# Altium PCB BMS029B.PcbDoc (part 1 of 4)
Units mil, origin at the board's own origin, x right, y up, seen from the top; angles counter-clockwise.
Board outline 4950 x 4000 mil, 4 copper layers (Layer 1 - Top Layer, Layer 2 - GND, Layer 3 - Signal, Layer 4 - Bottom Layer), stack 61.4 mil thick; 370 components, 202 nets, 969 pads, 408 vias.
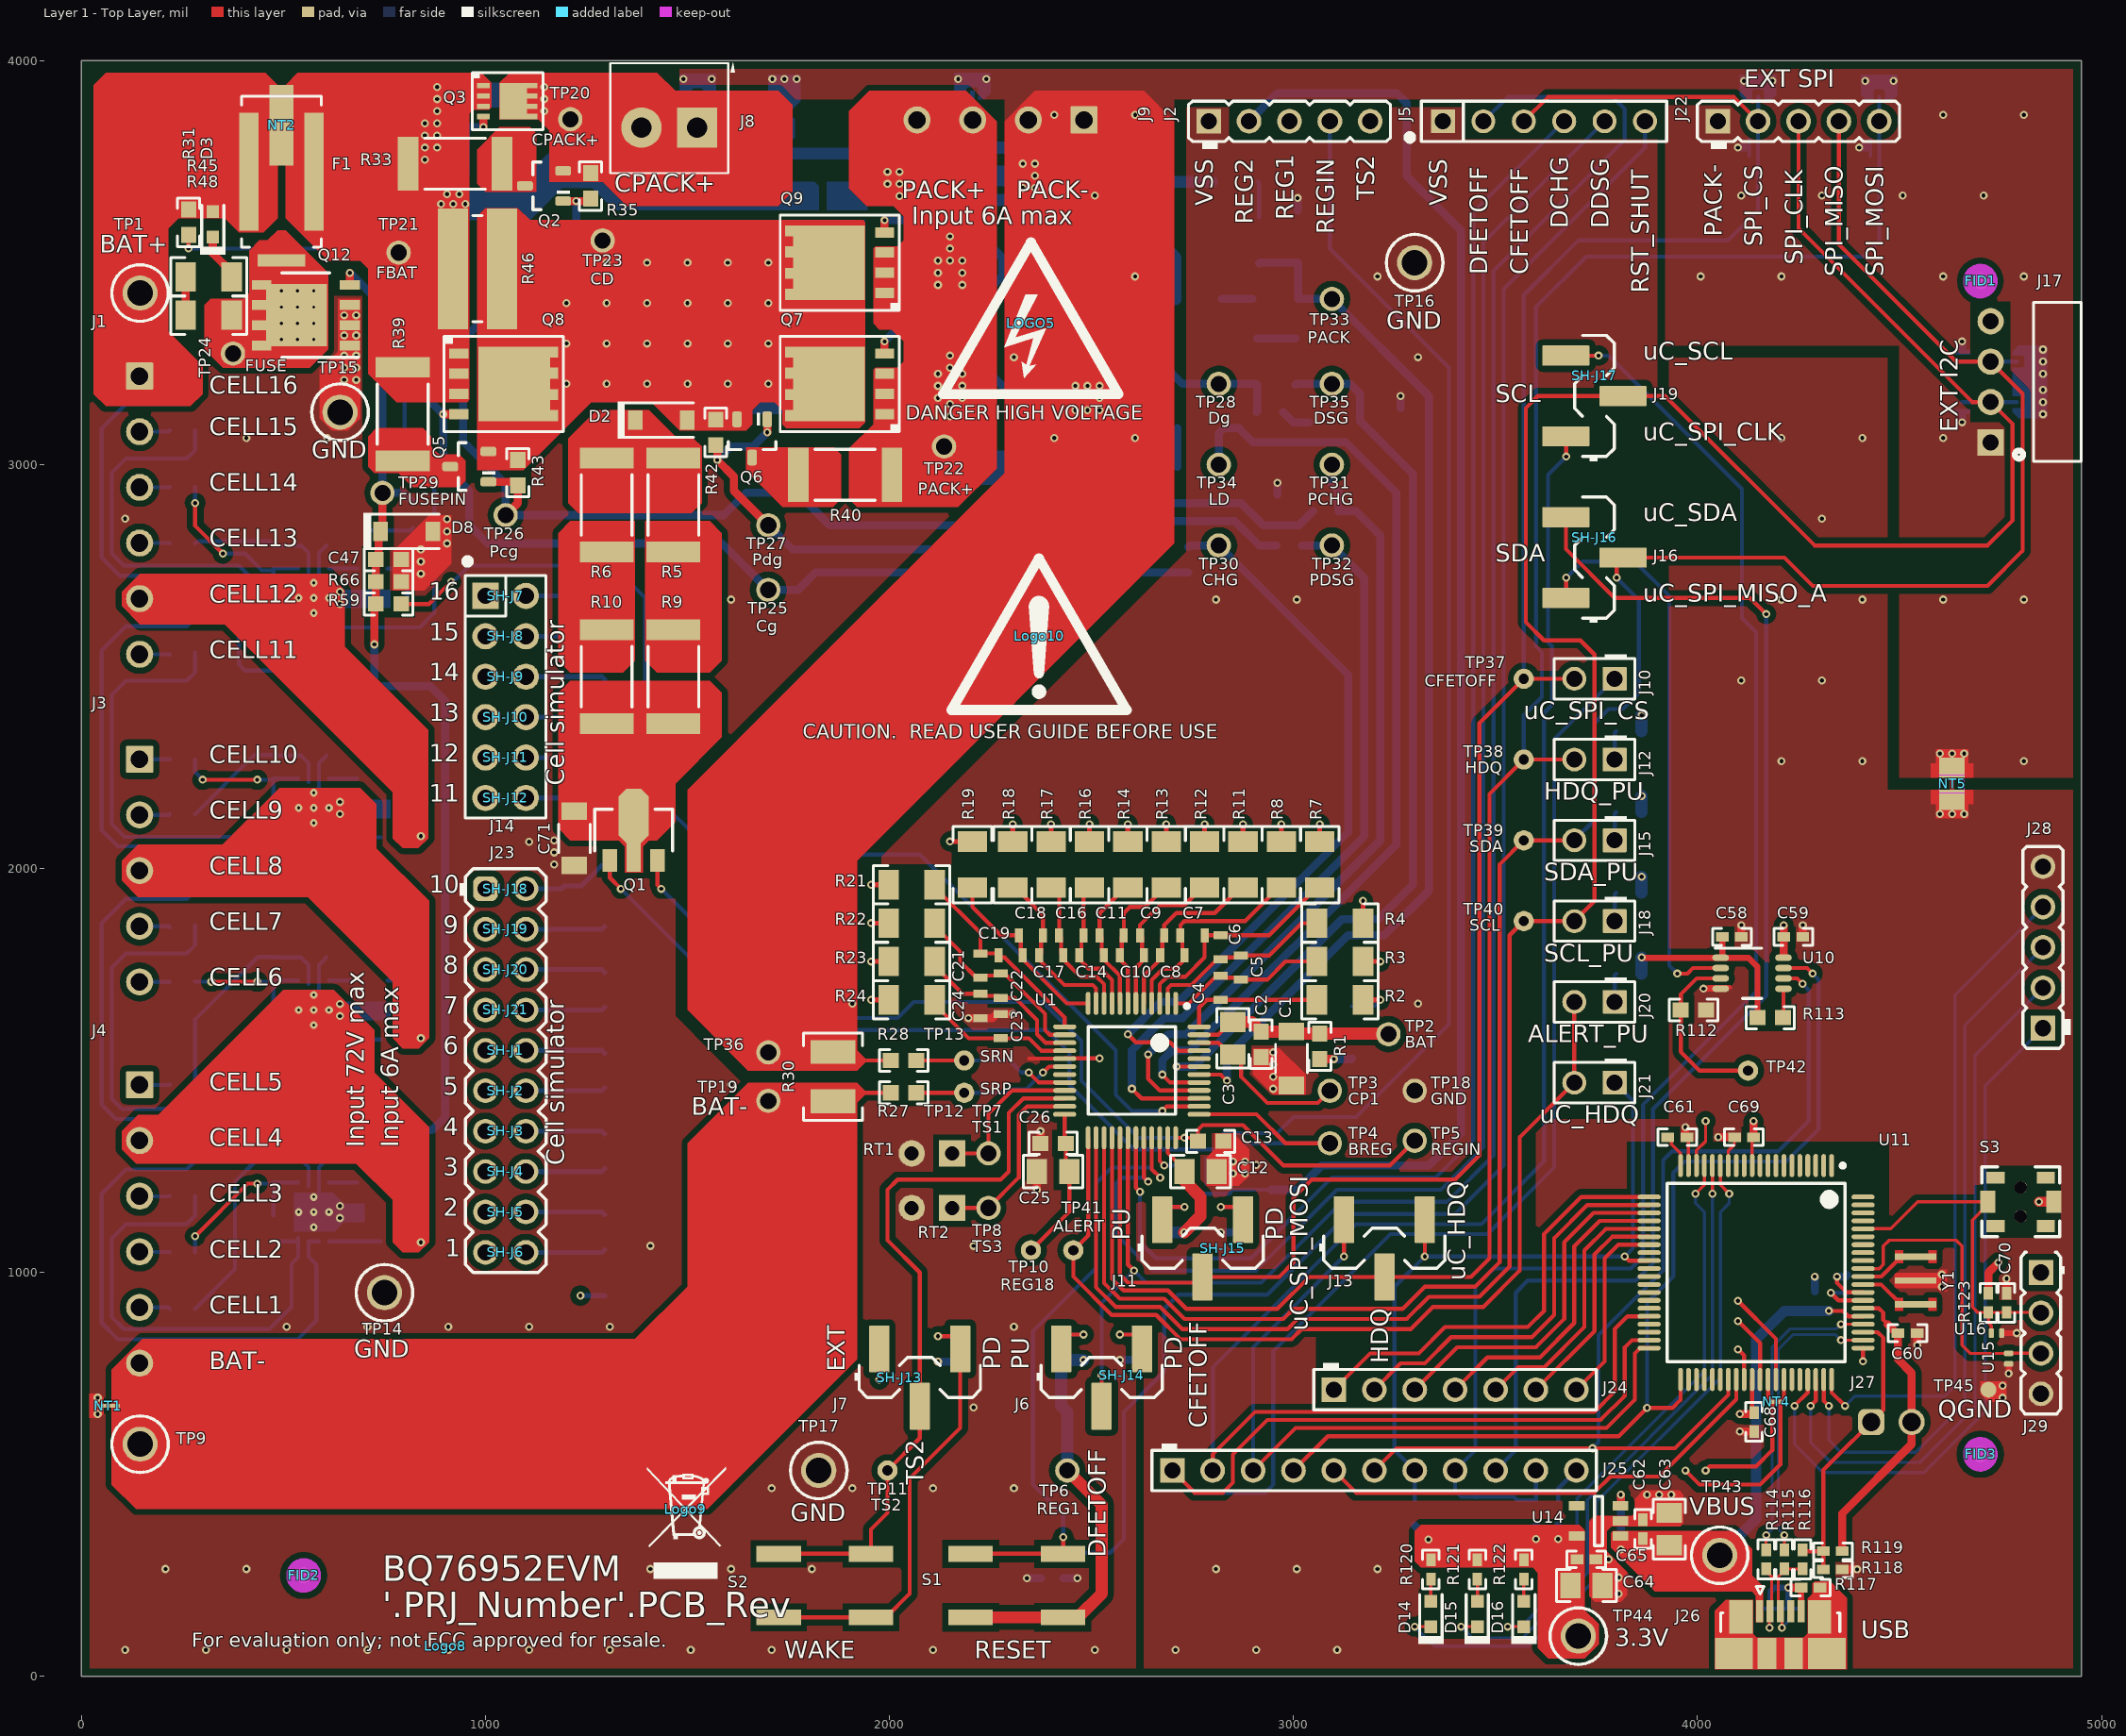
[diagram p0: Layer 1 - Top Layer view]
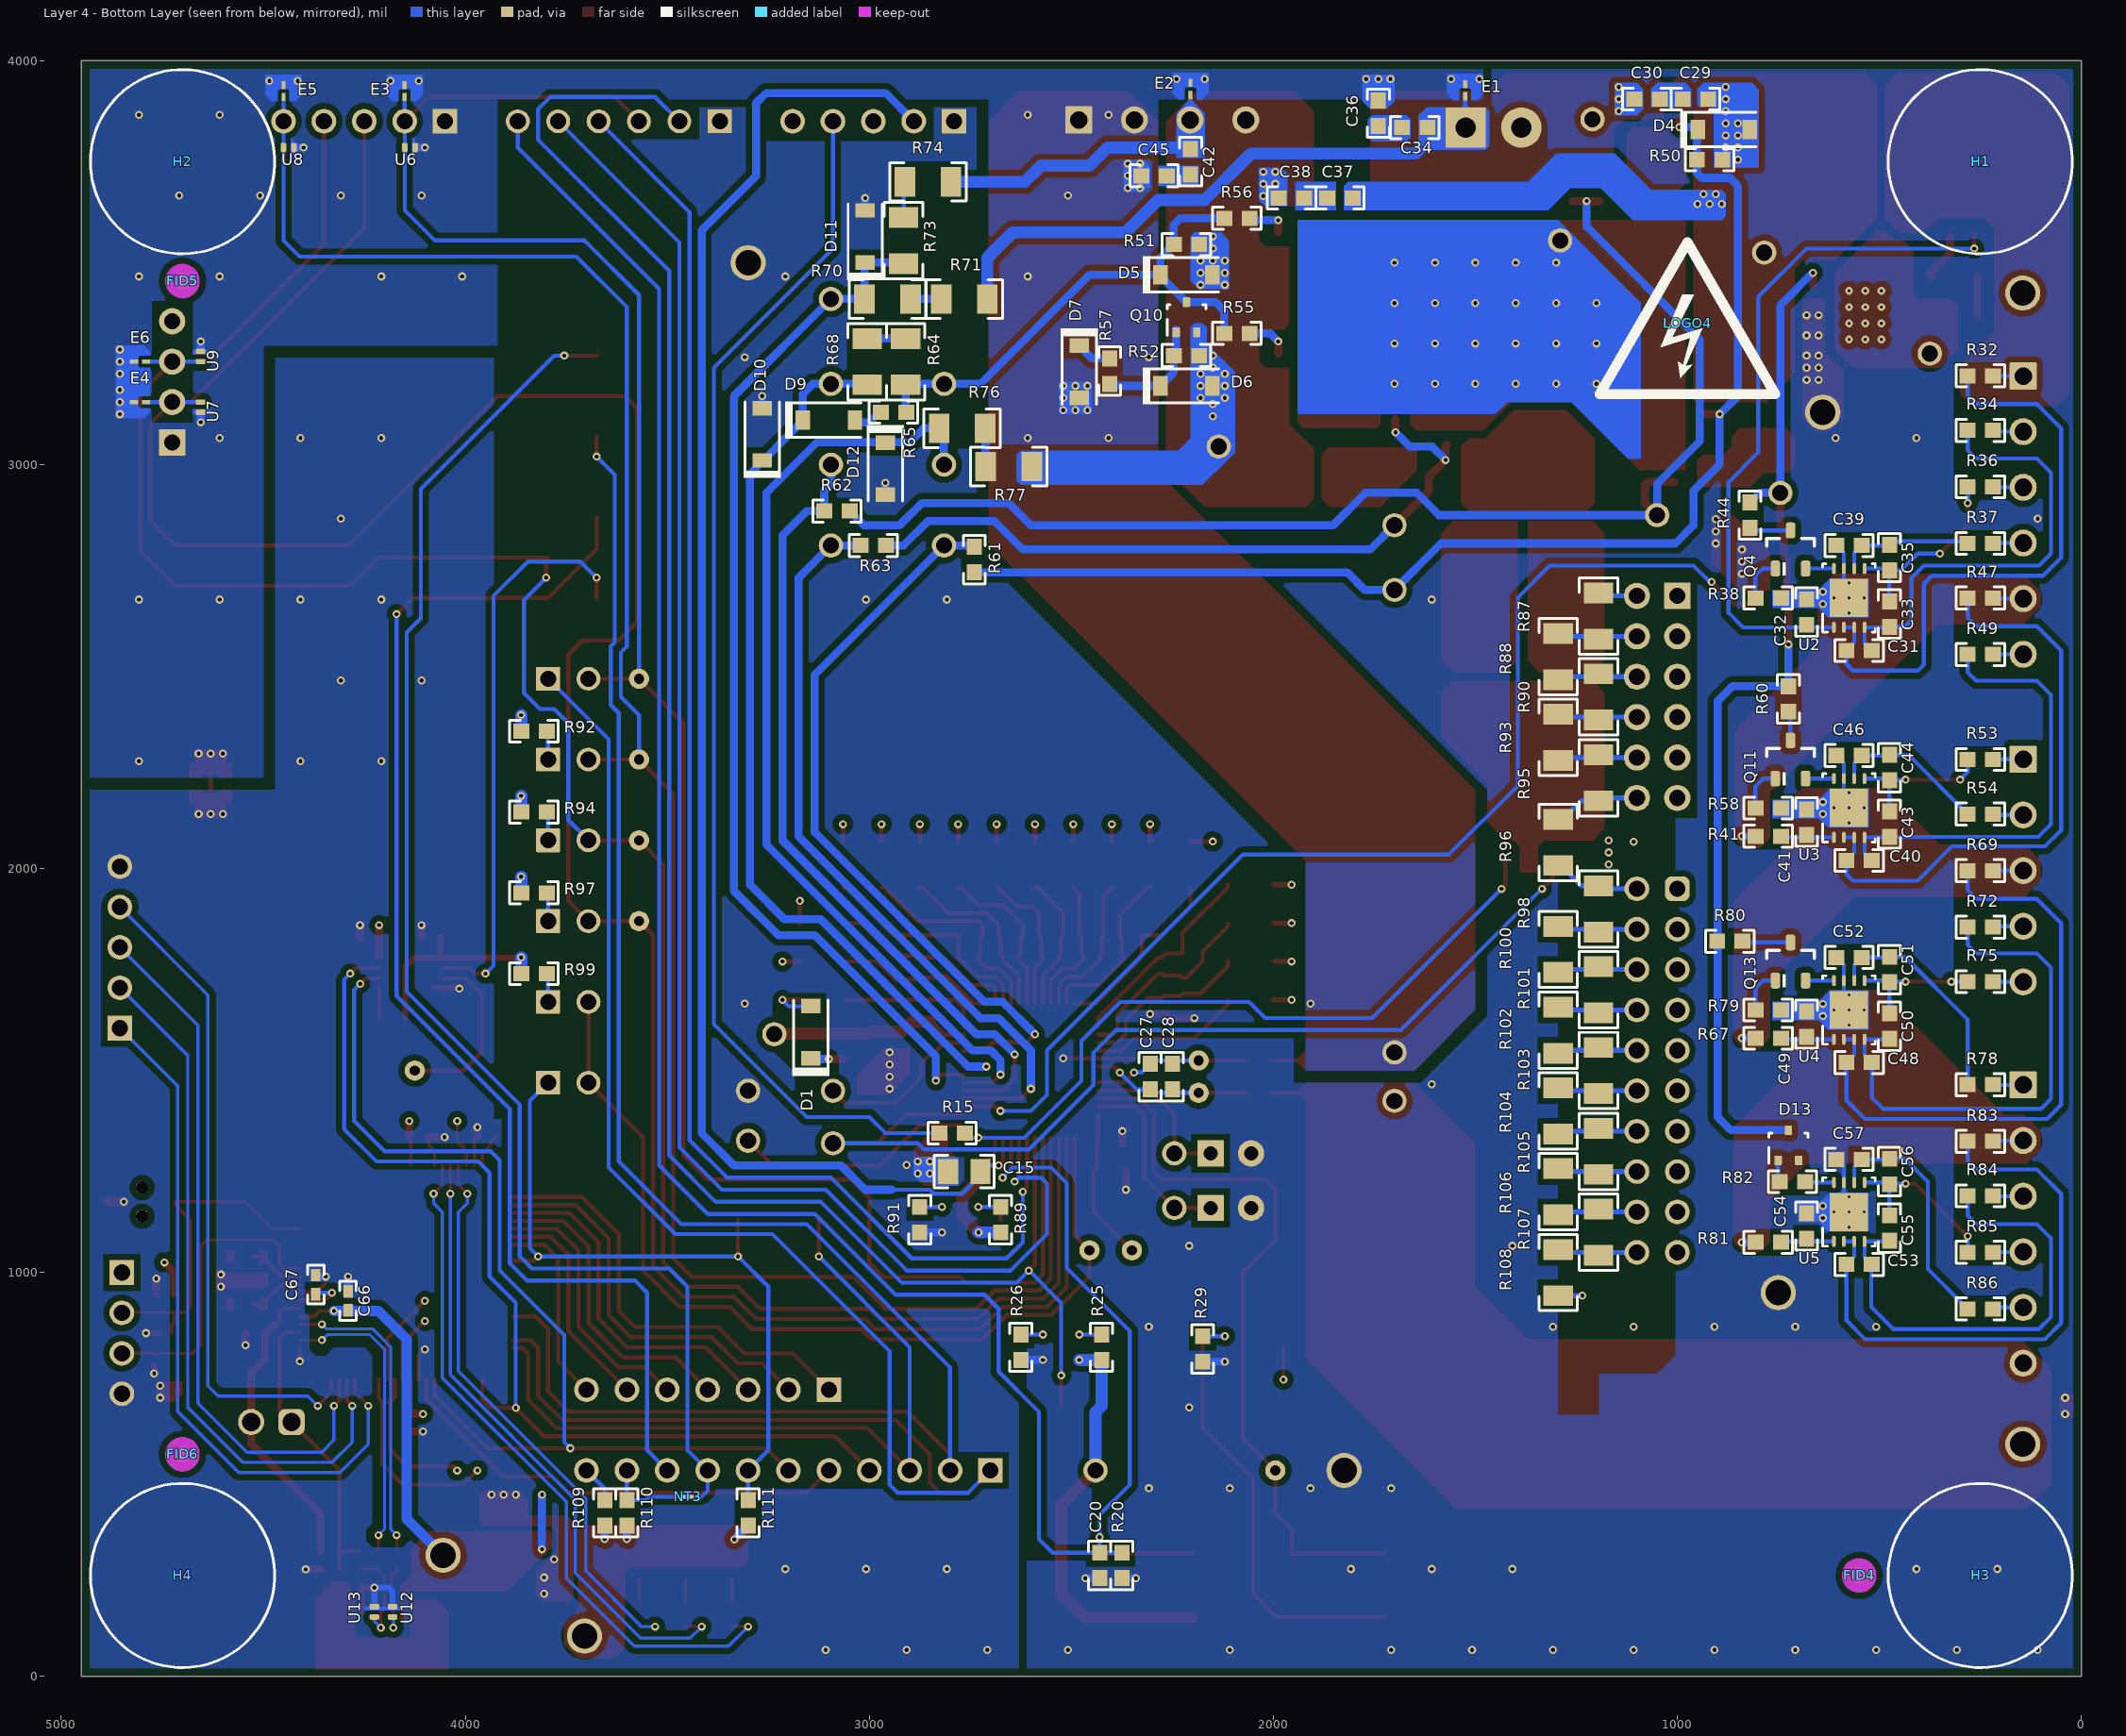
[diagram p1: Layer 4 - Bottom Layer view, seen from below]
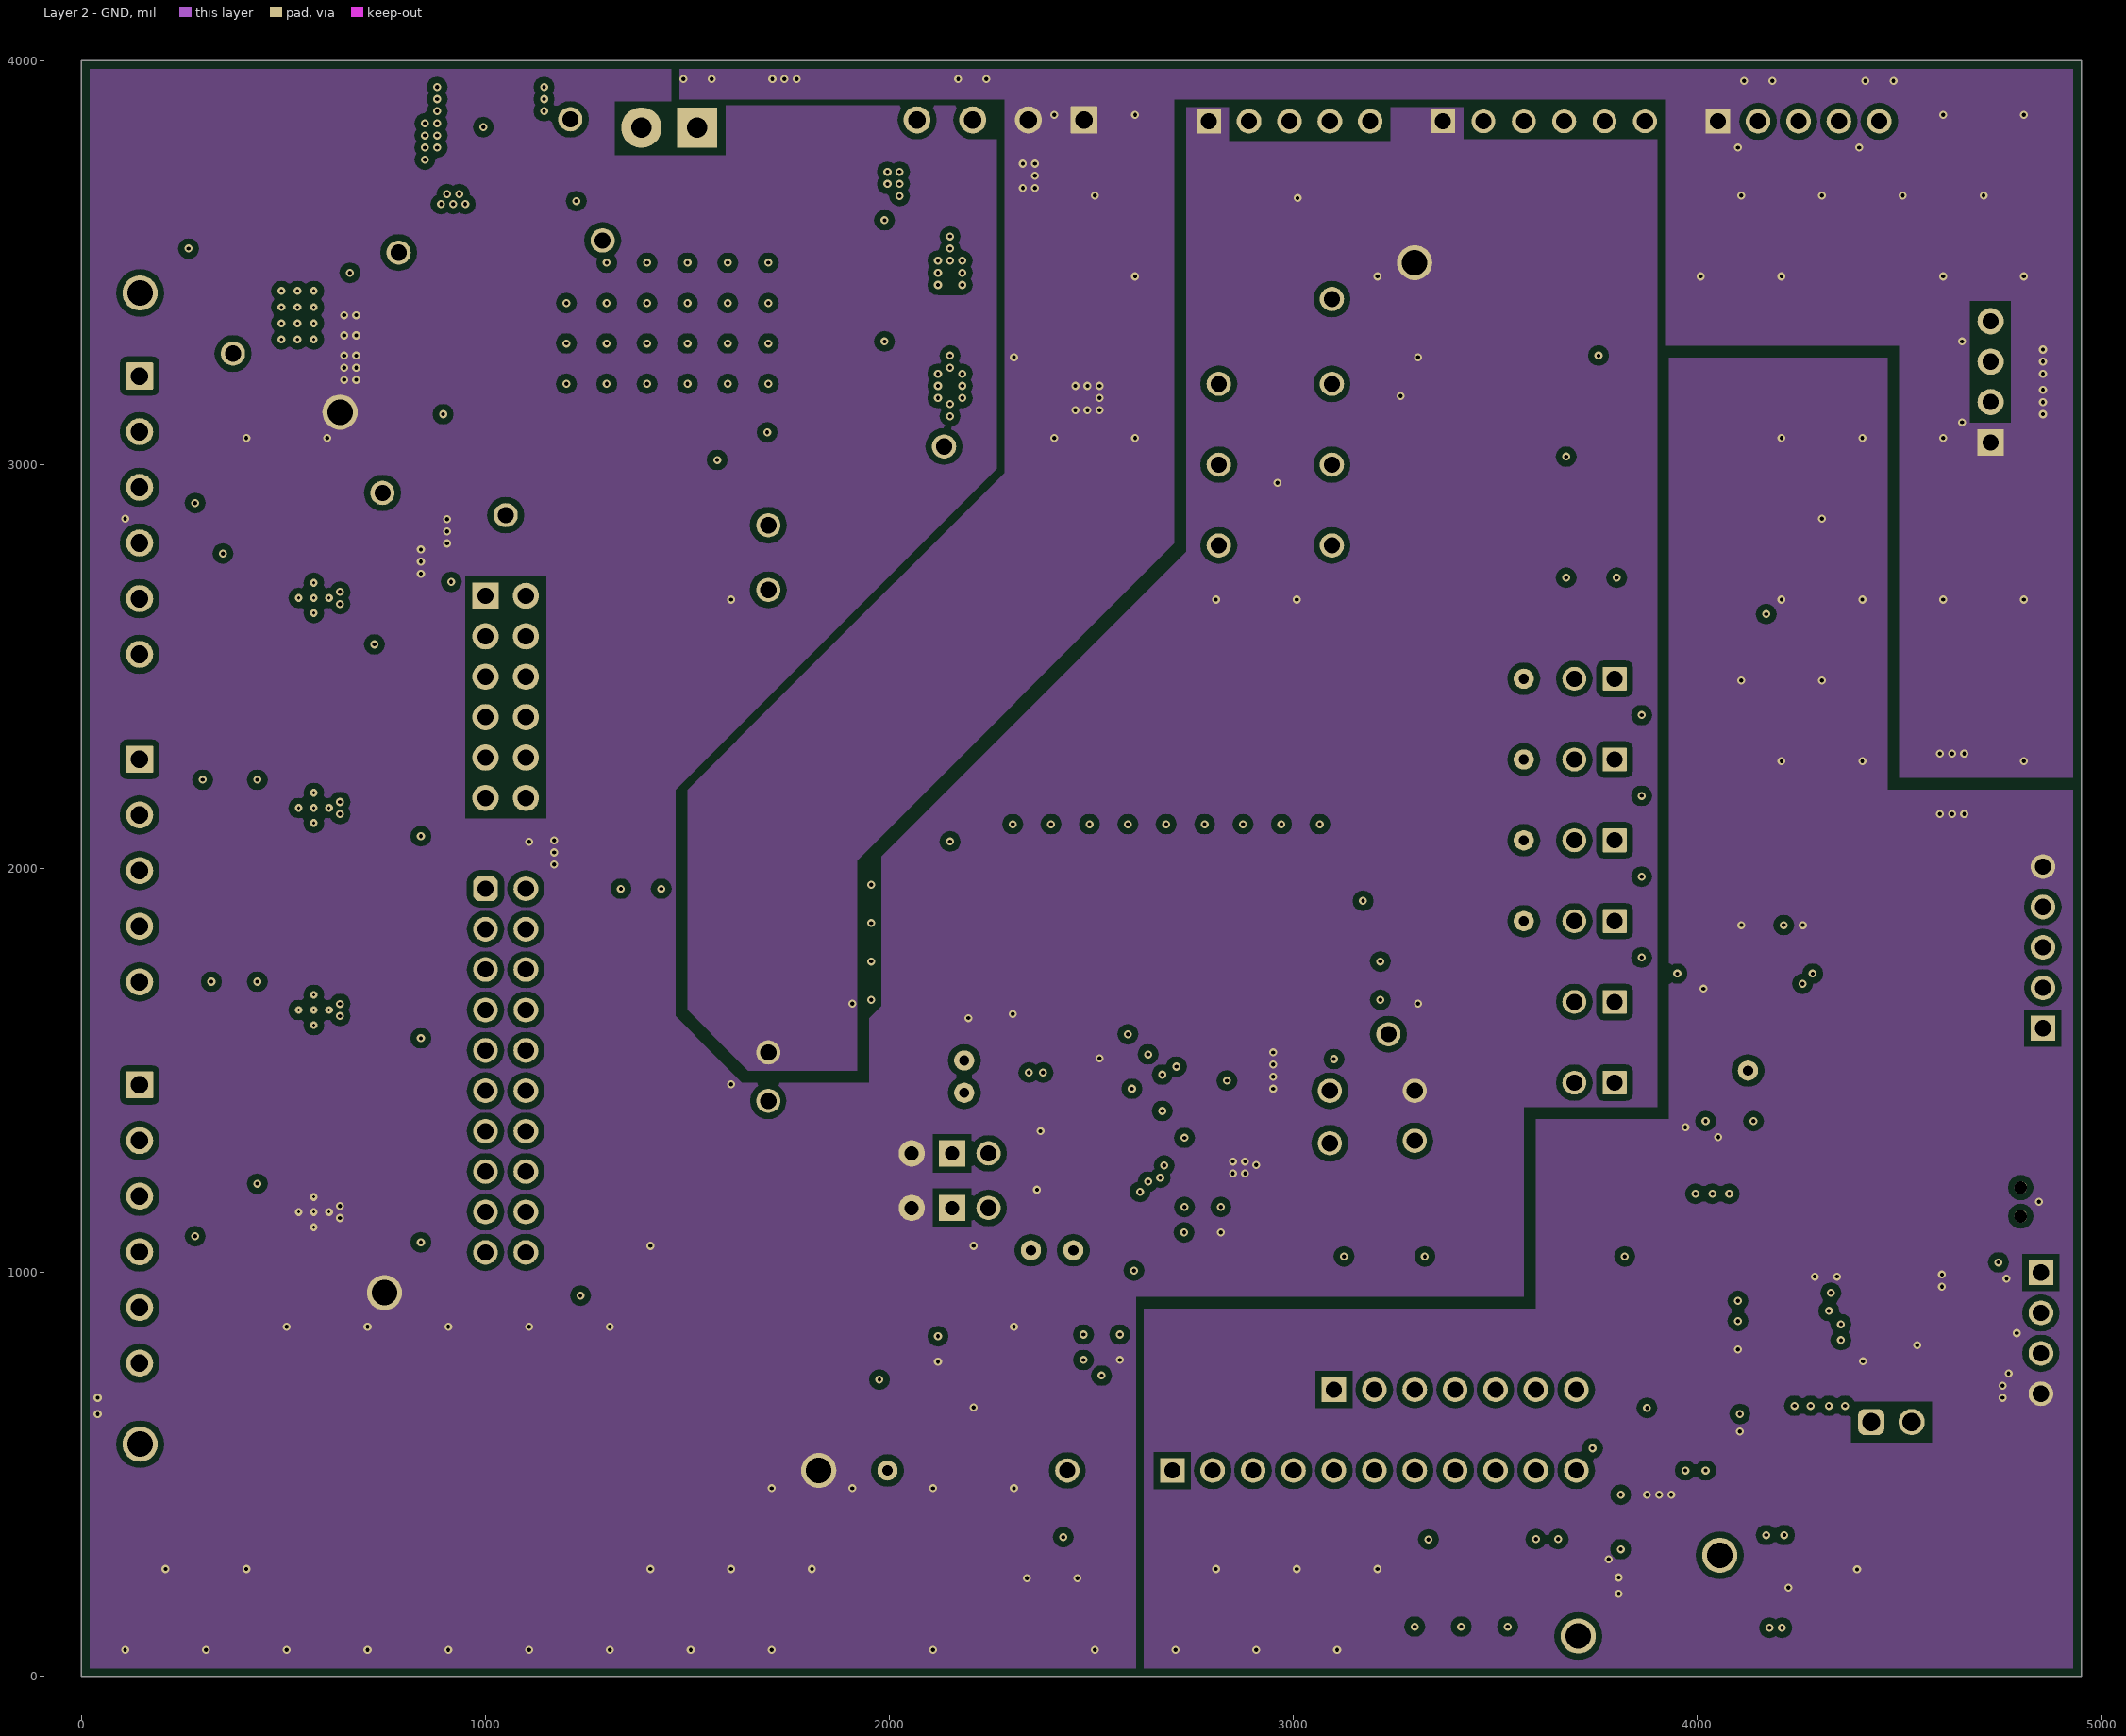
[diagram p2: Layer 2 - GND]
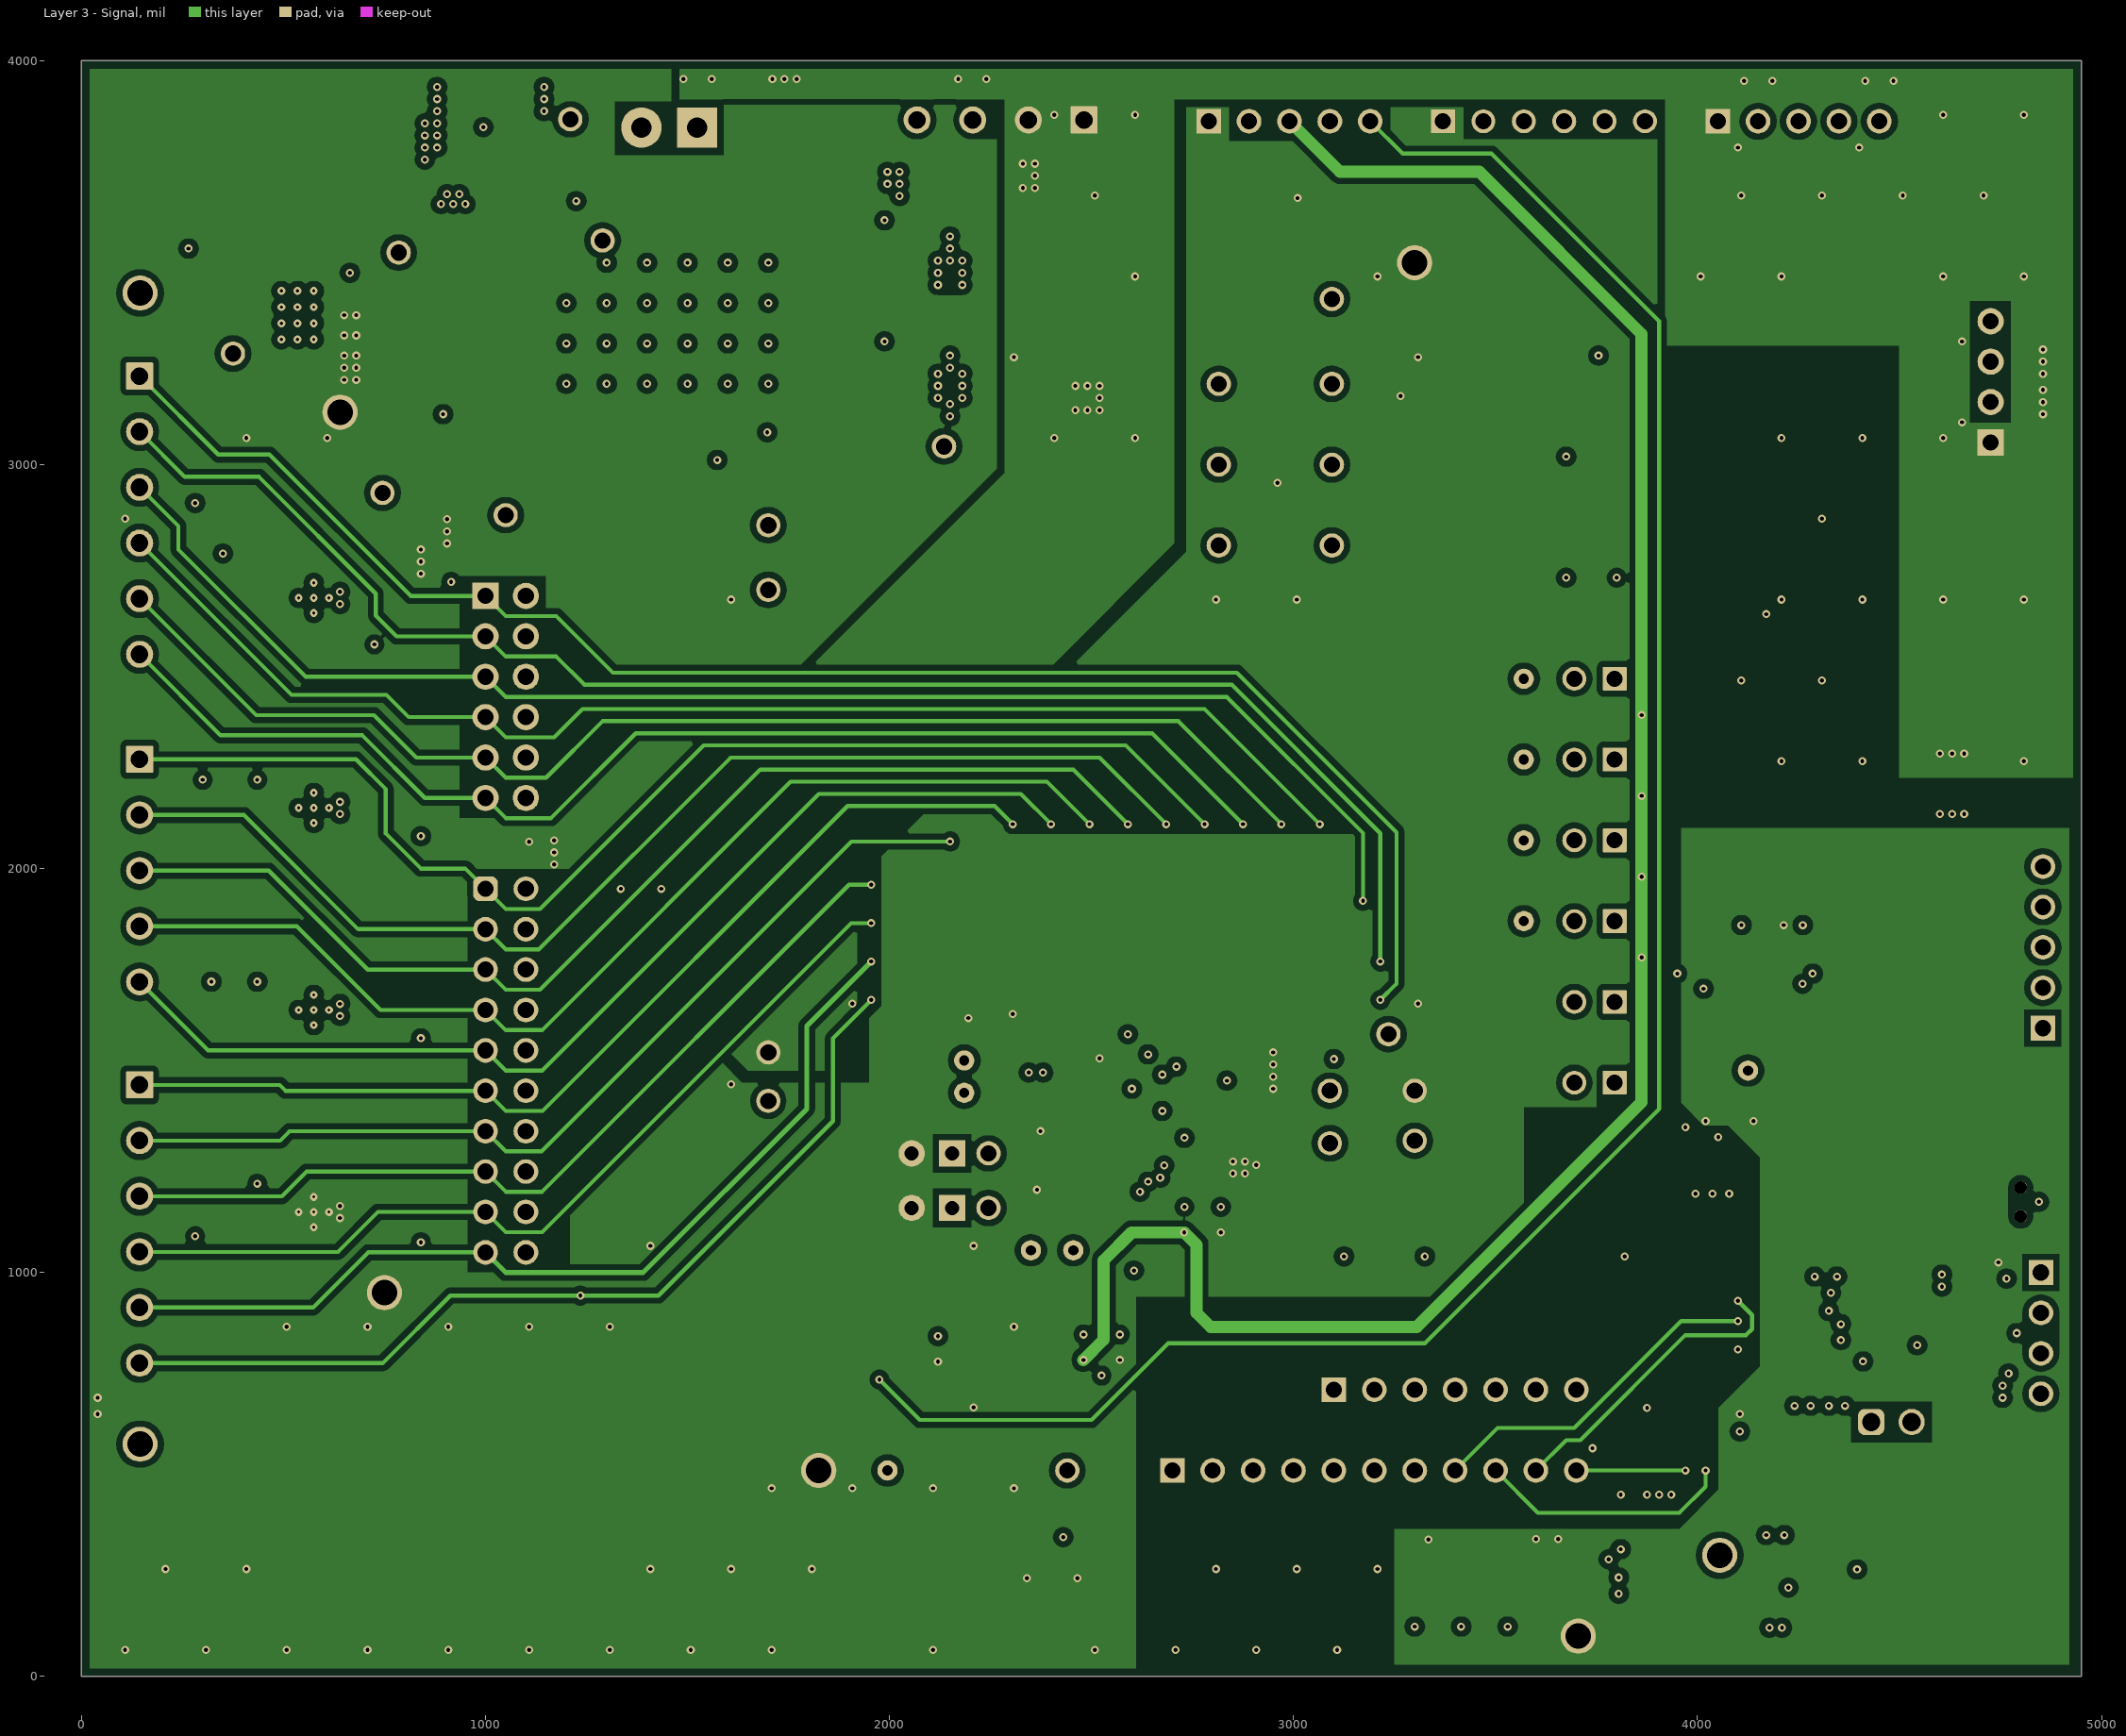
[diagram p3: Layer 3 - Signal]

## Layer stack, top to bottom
Top Solder: solder mask 0.4, Solder Resist, Dk 3.5
Layer 1 - Top Layer: signal copper 2.8
Dielectric 1: prepreg 6, FR-4 High Tg, Dk 4.2
Layer 2 - GND: signal copper 1.4
Dielectric 2: core 41, FR-4 High Tg, Dk 4.2
Layer 3 - Signal: signal copper 1.4
Dielectric 3: prepreg 6, FR-4 High Tg, Dk 4.2
Layer 4 - Bottom Layer: signal copper 2.8
Bottom Solder: solder mask 0.4, Solder Resist, Dk 3.5

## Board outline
0,0 0,4000 4950,4000 4950,0

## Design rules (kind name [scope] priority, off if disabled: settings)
AcuteAngle [All] p1: minimum=4.50000000000000E+0001 checktracksonly=FALSE
AssemblyTestPointUsage [All] p1: valid=2
BoardOutlineClearance BoardOutlineClearance_MountingHoles [OnCopper and InComponentClass('Mounting Holes')] p1: gap=39.37 ignorepadtopadclearanceinfootprint=FALSE
BoardOutlineClearance BoardOutlineClearance_Poly [OnCopper and IsPoly] p2: gap=20 ignorepadtopadclearanceinfootprint=FALSE
BoardOutlineClearance [OnCopper and Not InComponentClass('Logo') and not InComponentClass('FiducialMark') and not InRegion(1000,500,4000,800) and not InPoly] p3: gap=18 ignorepadtopadclearanceinfootprint=FALSE
Clearance Clearance_Keepouts [((IsTrack Or IsArc) And Not InPoly) And IsFree and IsKeepOut vs ((IsTrack Or IsArc) And Not InPoly) And IsFree and IsKeepOut] p1: gap=0 ignorepadtopadclearanceinfootprint=FALSE
Clearance Clearance_Poly [InPolygon] p2: gap=15 ignorepadtopadclearanceinfootprint=FALSE except(0: Arc-Hole Track-Hole SMDPad-Hole THPad-Hole Via-Hole Fill-Hole Poly-Hole Region-Hole Text-Hole)
Clearance Clearance_FiducialMark [IsKeepOut and InComponentClass('FiducialMark') vs IsPad and InComponentClass('FiducialMark')] p3: gap=0 ignorepadtopadclearanceinfootprint=FALSE
Clearance [All] p4: gap=7.87 ignorepadtopadclearanceinfootprint=FALSE except(0: Arc-Hole Track-Hole SMDPad-Hole THPad-Hole Via-Hole Fill-Hole Poly-Hole Region-Hole Text-Hole)
ComponentClearance "ComponentClearance_TP / Logo" [HasFootprint('IEC_HotSurface_Medium')] p1: gap=0 collisioncheckmode=3 verticalgap=0 showdistances=FALSE // IEC_HotSurface_Medium
ComponentClearance ComponentClearance_Net-tie [HasFootprint('Net-Tie_10mil') or HasFootprint('Net-Tie_50milWide_30milLong')] p2: gap=0 collisioncheckmode=3 verticalgap=0 showdistances=FALSE
ComponentClearance ComponentClearance_MountingHoles_FiducialMarks [InComponentClass('Mounting Holes') vs InComponentClass('FiducialMark')] p3: gap=10 collisioncheckmode=3 verticalgap=10 showdistances=FALSE
ComponentClearance ComponentClearance_Shunt [HasFootprint('SNT-100-BK-G')] p4: gap=0 collisioncheckmode=3 verticalgap=0 showdistances=TRUE
ComponentClearance ComponentClearance_Logo [InComponentClass('Logo')] p5: gap=0 collisioncheckmode=3 verticalgap=0 showdistances=FALSE
ComponentClearance ComponentClearance_ScrewToNut [(HasFootprint('NY PMS 440 0025 PH')) vs (HasFootprint('Keystone_1902C'))] p6: gap=5 collisioncheckmode=3 verticalgap=10 showdistances=FALSE
ComponentClearance ComponentClearance_MountingHoles [InComponentClass('Mounting Holes')] p7: gap=250 collisioncheckmode=3 verticalgap=100000 showdistances=FALSE
ComponentClearance ComponentClearance_SmallPassives [HasFootprint('0201*') or HasFootprint('0402*') or HasFootprint('0508') or HasFootprint('0603*') or HasFootprint('0612') or HasFootprint('0805*') or HasFootprint('0815*') or HasFootprint('0830*') or HasFootprint('1206*') or HasFootprint('1210*') or HasFootprint('1808*') or HasFootprint('1812*') or HasFootprint('1825*') or HasFootprint('2010*') or HasFootprint('2220*') or HasFootprint('2225*') or HasFootprint('2512*') or HasFootprint('2728*') or HasFootprint('3518*') vs HasFootprint('0201*') or HasFootprint('0402*') or HasFootprint('0508') or HasFootprint('0603*') or HasFootprint('0612') or HasFootprint('0805*') or HasFootprint('0815*') or HasFootprint('0830*') or HasFootprint('1206*') or HasFootprint('1210*') or HasFootprint('1808*') or HasFootprint('1812*') or HasFootprint('1825*') or HasFootprint('2010*') or HasFootprint('2220*') or HasFootprint('2225*') or HasFootprint('2512*') or HasFootprint('2728*') or HasFootprint('3518*')] p8: gap=10 collisioncheckmode=3 verticalgap=10 showdistances=FALSE
ComponentClearance ComponentClearance_THtoSMT [IsThruComponent vs IsSMTComponent] p9: gap=10 collisioncheckmode=3 verticalgap=30 showdistances=FALSE
ComponentClearance ComponentClearance_THtoTH [IsThruComponent vs IsThruComponent] p10: gap=10 collisioncheckmode=3 verticalgap=30 showdistances=FALSE
ComponentClearance [All] p11: gap=10 collisioncheckmode=3 verticalgap=10 showdistances=FALSE
DiffPairsRouting [All] p1: maxlimit=100 minlimit=10 mostfreqgap=10 toplayer_minwidth=15 toplayer_maxwidth=15 toplayer_prefwidth=15 midlayer1_minwidth=15 midlayer1_maxwidth=15 midlayer1_prefwidth=15 midlayer2_minwidth=15 midlayer2_maxwidth=15 midlayer2_prefwidth=15 bottomlayer_minwidth=15 bottomlayer_maxwidth=15 bottomlayer_prefwidth=15 maxuncoupledlength=1000
FabricationTestPointUsage TestPointUsage [All] p1: valid=2 allowmultiple=FALSE
FabricationTestpoint Testpoint [All] p1: side=3 testpointundercomponent=TRUE minsize=40 maxsize=100 preferedsize=60 minholesize=0 maxholesize=40 preferedholesize=32 testpointgrid=1 allowsidetop=TRUE allowsidebottom=TRUE usegrid=TRUE gridtolerance=0.01
FanoutControl Fanout_LCC [IsLCC] p1: bgadir=Out bgaviamode=Centered fanoutstyle=Auto fanoutdirection=Alternating viagrid=1 // Fanout_LCC (Default Rule)
FanoutControl Fanout_BGA [IsBGA] p2: bgadir=Out bgaviamode=Centered fanoutstyle=Auto fanoutdirection=Alternating viagrid=1 // Fanout_BGA (Default Rule)
FanoutControl Fanout_Default [All] p4: bgadir=Out bgaviamode=Centered fanoutstyle=Auto fanoutdirection=Alternating viagrid=1 // Fanout_Default (Default Rule)
FanoutControl Fanout_Small [(CompPinCount < 5)] p5: bgadir=Out bgaviamode=Centered fanoutstyle=Auto fanoutdirection=OutThenIn viagrid=1 // Fanout_Small (Default Rule)
HoleSize [All] p1: absolutevalues=TRUE maxlimit=251 minlimit=7.87 maxpercent=80.000 minpercent=20.000
MinimumAnnularRing MinimumAnnularRing_ThermalPadVias [IsVia and InAnyComponent] p1: minimumring=5.91
MinimumAnnularRing [All] p2: minimumring=5
MinimumSolderMaskSliver MinimumSolderMaskSliver_Logo [InComponentClass('Logo') vs InComponentClass('Logo')] p1: minsoldermaskwidth=0.7
MinimumSolderMaskSliver [All] p2: minsoldermaskwidth=3.9
PlaneConnect [All] p1: planeconnectstyle=Relief reliefexpansion=10 reliefentries=4 reliefconductorwidth=10 reliefairgap=10
PolygonConnect [All] p1: connectstyle=Direct reliefconductorwidth=10 reliefentries=4 polygonreliefangle="90 Angle" airgapwidth=10
RoutingVias ThermalPadVias [IsVia and InAnyComponent] p1: holewidth=7.87 width=19.68 viastyle="Through Hole" minholewidth=7.87 minwidth=19.68 maxholewidth=12.99 maxwidth=23.62
RoutingVias [All] p2: holewidth=16 width=34 viastyle="Through Hole" minholewidth=7.87 minwidth=20 maxholewidth=40 maxwidth=65
SilkToBoardRegionClearance [Not ((IsComment or IsDesignator) And (Hide <> 'False')) and not InRegion(1000,500,4000,800)] p1:
SilkToSilkClearance SilkToSilkClearance_Pb-FreeLogo [(HasFootprint('Pb-Free_Overlay_Medium') OR HasFootprint('Pb-Free_Overlay_Small')) vs (HasFootprint('Pb-Free_Overlay_Medium') OR HasFootprint('Pb-Free_Overlay_Small'))] p1: silktosilkclearance=0
SilkToSilkClearance [All] p2: silktosilkclearance=3.9
SilkToSolderMaskClearance SilkToComponentPadClearance [(IsPad or IsFill or IsRegion) and InAnycomponent] p1: minsilkscreentomaskgap=5 clearancetoexposedcopper=TRUE
SilkToSolderMaskClearance "Silk to Solder Mask Opening" [All] p2: minsilkscreentomaskgap=3.94 clearancetoexposedcopper=FALSE
SolderMaskExpansion [All] p1: expansion=1.97
Width [All] p1: maxlimit=100 minlimit=6 preferedwidth=10 checkconnectedcopper=TRUE
15 further rules are at their usual default settings.

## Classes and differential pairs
component class Shunt: SH-J1 SH-J2 SH-J3 SH-J4 SH-J5 SH-J6 SH-J7 SH-J8 SH-J9 SH-J10 SH-J11 SH-J12 SH-J13 SH-J14 SH-J15 SH-J16 SH-J17 SH-J18 SH-J19 SH-J20 SH-J21
component class Header: J2 J5 J6 J7 J10 J11 J12 J13 J14 J15 J16 J18 J19 J20 J21 J22 J23 J24 J25 J27 J28 J29
component class BMS029B_PinConfig: E3 E4 E5 E6 J10 J11 J12 J13 J14 J15 J16 J17 J18 J19 J20 J21 J22 J23 R87 R88 R89 R90 R91 R92 R93 R94 R95 R96 R97 R98 R99 R100 R101 R102 R103 R104 R105 R106 R107 R108 TP37 TP38 TP39 TP40 TP41 U6 U7 U8 U9
component class BMS029B_Monitor: C1 C2 C3 C4 C5 C6 C7 C8 C9 C10 C11 C12 C13 C14 C15 C16 C17 C18 C19 C20 C21 C22 C23 C24 C25 C26 C27 C28 C71 D1 D2 J1 J2 J3 J4 J5 J6 J7 NT1 Q1 R1 R2 R3 R4 R5 R6 R7 R8 R9 R10 R11 R12 R13 R14 R15 R16 R17 R18 R19 R20 R21 R22 R23 R24 R25 R26 R27 R28 R29 R30 RT1 RT2 S1 S2 TP1 TP2 TP3 TP4 TP5 TP6 TP7 TP8 TP9 TP10 TP11 TP12 TP13 TP14 TP15 TP16 TP17 TP18 TP19 U1
component class BMS029B_Interface: C58 C59 C60 C61 C62 C63 C64 C65 C66 C67 C68 C69 C70 D14 D15 D16 J24 J25 J26 J27 J28 J29 NT3 NT4 NT5 R109 R110 R111 R112 R113 R114 R115 R116 R117 R118 R119 R120 R121 R122 R123 S3 TP42 TP43 TP44 TP45 U10 U11 U12 U13 U14 U15 U16 Y1
component class BMS029B_FETs: C29 C30 C31 C32 C33 C34 C35 C36 C37 C38 C39 C40 C41 C42 C43 C44 C45 C46 C47 C48 C49 C50 C51 C52 C53 C54 C55 C56 C57 D3 D4 D5 D6 D7 D8 D9 D10 D11 D12 D13 E1 E2 F1 J8 J9 NT2 Q2 Q3 Q4 Q5 Q6 Q7 Q8 Q9 Q10 Q11 Q12 Q13 R31 R32 R33 R34 R35 R36 R37 R38 R39 R40 R41 R42 R43 R44 R45 R46 R47 R48 R49 R50 R51 R52 R53 R54 R55 R56 R57 R58 R59 R60 R61 R62 R63 R64 R65 R66 R67 R68 R69 R70 R71 R72 R73 R74 R75 R76 R77 R78 R79 R80 R81 R82 R83 R84 R85 R86 TP20 TP21 TP22 TP23 TP24 TP25 TP26 TP27 TP28 TP29 TP30 TP31 TP32 TP33 TP34 TP35 TP36 U2 U3 U4 U5
component class BMS029B_Hardware: FID1 FID2 FID3 FID4 FID5 FID6 H1 H2 H3 H4 LOGO4 LOGO5 Logo8 Logo9 Logo10 SH-J1 SH-J2 SH-J3 SH-J4 SH-J5 SH-J6 SH-J7 SH-J8 SH-J9 SH-J10 SH-J11 SH-J12 SH-J13 SH-J14 SH-J15 SH-J16 SH-J17 SH-J18 SH-J19 SH-J20 SH-J21 ZZ1 ZZ2 ZZ3
component class FiducialMark: FID1 FID2 FID3 FID4 FID5 FID6
component class AssemblyNote: ZZ1 ZZ2 ZZ3

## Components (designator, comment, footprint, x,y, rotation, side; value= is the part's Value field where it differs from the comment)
C1 "C3216X7R2A105K160AA" 1206_180 2995,1530 r270 top value=1uF
C2 "GCM1885C2A101JA16D" 0603 2920,1565 r270 top value=100pF
C3 "GCM219R71E474KA55D" 0805_HV 2850,1580 r270 top value=0.47uF
C4 "C1608X7R1H224K080AB" 0603S 2820,1705 r90 top value=0.22uF
C5 "C1608X7R1H224K080AB" 0603S 2870,1755 r90 top value=0.22uF
C6 "C1608X7R1H224K080AB" 0603S 2820,1805 r90 top value=0.22uF
C7 "C1608X7R1H224K080AB" 0603S 2750,1835 r180 top value=0.22uF
C8 "C1608X7R1H224K080AB" 0603S 2700,1785 r180 top value=0.22uF
C9 "C1608X7R1H224K080AB" 0603S 2650,1835 r180 top value=0.22uF
C10 "C1608X7R1H224K080AB" 0603S 2600,1785 r180 top value=0.22uF
C11 "C1608X7R1H224K080AB" 0603S 2550,1835 r180 top value=0.22uF
C12 "EMK212B7105KG-T" 0805_HV 2770,1250 r180 top value=1uF
C13 "C0603C223K4RACTU" 0603 2795,1325 r180 top value=0.022uF
C14 "C1608X7R1H224K080AB" 0603S 2500,1785 r180 top value=0.22uF
C15 "EMK212B7105KG-T" 0805_HV 2765,1250 r180 bottom value=1uF
C16 "C1608X7R1H224K080AB" 0603S 2450,1835 r180 top value=0.22uF
C17 "C1608X7R1H224K080AB" 0603S 2400,1785 r180 top value=0.22uF
C18 "C1608X7R1H224K080AB" 0603S 2350,1835 r180 top value=0.22uF
C19 "C1608X7R1H224K080AB" 0603S 2300,1785 r180 top value=0.22uF
C20 "885012206040" 0603 2430,275 r270 bottom value=0.01uF
C21 "C1608X7R1H224K080AB" 0603S 2225,1760 r270 top value=0.22uF
C22 "C1608X7R1H224K080AB" 0603S 2275,1710 r270 top value=0.22uF
C23 "C1608X7R1H224K080AB" 0603S 2275,1610 r90 top value=0.22uF
C24 "C1608X7R1H224K080AB" 0603S 2225,1660 r270 top value=0.22uF
C25 "EMK212B7225KG-T" 0805_HV 2405,1250 r0 top value=2.2uF
C26 "885012206040" 0603 2405,1320 r180 top value=0.01uF
C27 "C0603C101J5GACTU" 0603 2305,1485 r270 bottom value=100pF
C28 "885012206095" 0603 2250,1485 r90 bottom value=0.1uF
C29 "GCJ188R72A104KA01D" 0603 955,3905 r180 bottom value=0.1uF
C30 "GCJ188R72A104KA01D" 0603 1075,3905 r180 bottom value=0.1uF
C31 "885012206095" 0603 550,2540 r0 bottom value=0.1uF
C32 "885012206095" 0603 680,2635 r270 bottom value=0.1uF
C33 "885012206095" 0603 475,2630 r270 bottom value=0.1uF
C34 "GCJ188R72A104KA01D" 0603 1650,3834.5 r0 bottom value=0.1uF
C35 "885012206095" 0603 475,2770 r270 bottom value=0.1uF
C36 "GCJ188R72A104KA01D" 0603 1740,3870 r90 bottom value=0.1uF
C37 "GCJ188R72A104KA01D" 0603 1835,3660 r180 bottom value=0.1uF
C38 "GCJ188R72A104KA01D" 0603 1955,3660 r180 bottom value=0.1uF
C39 "885012206095" 0603 575,2800 r180 bottom value=0.1uF
C40 "885012206095" 0603 550,2020 r0 bottom value=0.1uF
C41 "885012206095" 0603 680,2115 r270 bottom value=0.1uF
C42 "GCJ188R72A104KA01D" 0603 2205,3750 r270 bottom value=0.1uF
C43 "885012206095" 0603 475,2110 r270 bottom value=0.1uF
C44 "885012206095" 0603 475,2250 r270 bottom value=0.1uF
C45 "GCJ188R72A104KA01D" 0603 2295,3715 r0 bottom value=0.1uF
C46 "885012206095" 0603 575,2280 r180 bottom value=0.1uF
C47 "885012206095" 0603 760,2765 r180 top value=0.1uF
C48 "885012206095" 0603 550,1520 r0 bottom value=0.1uF
C49 "885012206095" 0603 680,1615 r270 bottom value=0.1uF
C50 "885012206095" 0603 475,1610 r270 bottom value=0.1uF
C51 "885012206095" 0603 475,1750 r270 bottom value=0.1uF
C52 "885012206095" 0603 575,1780 r180 bottom value=0.1uF
C53 "885012206095" 0603 550,1020 r0 bottom value=0.1uF
C54 "885012206095" 0603 680,1115 r270 bottom value=0.1uF
C55 "885012206095" 0603 475,1110 r270 bottom value=0.1uF
C56 "885012206095" 0603 475,1250 r270 bottom value=0.1uF
C57 "885012206095" 0603 575,1280 r180 bottom value=0.1uF
C58 "885012205037" 0402 4085,1831 r180 top value=0.1uF
C59 "885012205037" 0402 4237,1831 r180 top value=0.1uF
C60 "885012205037" 0402 4520,850 r0 top value=0.1uF
C61 "Capacitor" 0402 3950,1335 r0 top value=0.47uF
C62 "885012205037" 0402 3865,365 r90 top value=0.1uF
C63 "CL21A106KOQNNNG" 0805_HV 3930,365 r90 top value=10uF
C64 "CL21A106KOQNNNG" 0805_HV 3725,225 r0 top value=10uF
C65 "885012205037" 0402 3725,290 r0 top value=0.1uF
C66 "885012205037" 0402 4290,930 r90 bottom value=0.1uF
C67 "Capacitor" 0402 4370,970 r90 bottom value=0.47uF
C68 "885012205037" 0402 4140,630 r270 top value=0.1uF
C69 "Capacitor" 0402 4115,1335 r180 top value=0.47uF
C70 "885012205008" 0402 4765,925 r90 top value=2200pF
C71 "C3216X7R2A105K160AA" 1206_180 1220,2075 r270 top value=1uF
D1 "BAT46W-7-F" SOD-123 3145,1595 r90 bottom value=100V
D2 "BAT46W-7-F" SOD-123 1435,3110 r0 top value=100V
D3 "150060RS75000" WL-SMCW_RED 325,3595 r90 top value=Red
D4 "MMSZ5246B-7-F" SOD-123 885,3830 r180 bottom value=16V
D5 "MMSZ5246B-7-F" SOD-123 2215,3470 r180 bottom value=16V
D6 "MMSZ5246B-7-F" SOD-123 2215,3195 r180 bottom value=16V
D7 "1N4148W-7-F" SOD-123 2480,3230 r270 bottom value=100V
D8 "MMSZ4697T1G" SOD-123 805,2835 r0 top value=10V
D9 "BAT46W-7-F" SOD-123 3100,3110 r180 bottom value=100V
D10 "BAT46W-7-F" SOD-123 3265,3075 r90 bottom value=100V
D11 "BAT46W-7-F" SOD-123 3010,3565 r90 bottom value=100V
D12 "BAT46W-7-F" SOD-123 2960,2990 r270 bottom value=100V
D13 "BAS40W-7-F" SOT-323 725,1315 r90 bottom value=40V
D14 "150060VS75000" WL-SMCW_GREEN 3340,155 r90 top value=Green
D15 "150060VS75000" WL-SMCW_GREEN 3455,155 r90 top value=Green
D16 "150060VS75000" WL-SMCW_GREEN 3570,155 r90 top value=Green
E1 "Spark Gap" SPARK_GAP2 1525,3932 r0 bottom
E2 "Spark Gap" SPARK_GAP2 2205,3935 r0 bottom
E3 "Spark Gap" SPARK_GAP2 4150,3930 r0 bottom
E4 "Spark Gap" SPARK_GAP2 4810,3155 r270 bottom
E5 "Spark Gap" SPARK_GAP2 4450,3930 r0 bottom
E6 "Spark Gap" SPARK_GAP2 4810,3255 r270 bottom
F1 "SFK-3030" FUSE_SFK-xx30x 495,3725 r90 top
FID1 "Fiducial" Fiducial10-20 4700,3454.34 r0 top
FID2 "Fiducial" Fiducial10-20 550,250 r0 top
FID3 "Fiducial" Fiducial10-20 4700,550 r0 top
FID4 "Fiducial" Fiducial10-20 550,250 r180 bottom
FID5 "Fiducial" Fiducial10-20 4700,3454.34 r180 bottom
FID6 "Fiducial" Fiducial10-20 4700,550 r180 bottom
H1 "SJ-5303 (CLEAR)" Bumpon_SJ5003Transparent 250,3750 r180 bottom
H2 "SJ-5303 (CLEAR)" Bumpon_SJ5003Transparent 4700,3750 r180 bottom
H3 "SJ-5303 (CLEAR)" Bumpon_SJ5003Transparent 250,250 r180 bottom
H4 "SJ-5303 (CLEAR)" Bumpon_SJ5003Transparent 4700,250 r180 bottom
J1 "OSTTE060161" FP-OSTTE060161_HDR6-MFG 140,2875 r270 top
J2 "PEC05SAAN" Sullins_PxC05SAAN 2990,3850 r0 top
J3 "OSTTE050161" FP-OSTTE050161_HDR5-MFG 140,1995 r270 top
J4 "OSTTE060161" FP-OSTTE060161_HDR6-MFG 140,1120 r270 top
J5 "PEC06SAAN" Sullins_PEC06SAAN 3620,3850 r0 top
J6 "87898-0304" Molex_87898-0304 2525,740 r0 top
J7 "87898-0304" Molex_87898-0304 2075,740 r0 top
J8 "ED555/2DS" TERM_BLK_ED555-2DS 1524.01,3834.5 r180 top
J9 "OSTTE040161" FP-OSTTE040161_HDR4-MFG 2275.01,3857.5 r180 top
J10 "PEC02SAAN" CONN_PEC02SAAN 3745,2470 r180 top
J11 "87898-0304" Molex_87898-0304 2775,1060 r0 top
J12 "PEC02SAAN" CONN_PEC02SAAN 3745,2270 r180 top
J13 "87898-0304" Molex_87898-0304 3225,1060 r0 top
J14 "PEC06DAAN" CONN_PEC06DAAN 1050,2425 r270 top
J15 "PEC02SAAN" CONN_PEC02SAAN 3745,2070 r180 top
J16 "87898-0304" Molex_87898-0304 3745,2770 r90 top
J17 "22/05/3041" CONN_22-05-3041 4950,3205 r90 top
J18 "PEC02SAAN" CONN_PEC02SAAN 3745,1870 r180 top
J19 "87898-0304" Molex_87898-0304 3745,3170 r90 top
J20 "PEC02SAAN" CONN_PEC02SAAN 3745,1670 r180 top
J21 "PEC02SAAN" CONN_PEC02SAAN 3745,1470 r180 top
J22 "PEC05SAAN" Sullins_PxC05SAAN 4250,3850 r0 top
J23 "PEC10DAAN" SULLINS_PEC10DAAN 1050,1500 r0 top
J24 "PBC07SAAN" Sullins_xxC07SAAN 3400,710 r0 top
J25 "PBC11SAAN" Sullins_xxC11SAAN 3200,510 r0 top
J26 "CONN_USB_5Pos-6Shld" Molex_47346-1001 4205,0 r0 top
J27 "61300211121" WURTH_61300211121 4480,630 r0 top
J28 "PEC05SAAN" Sullins_PxC05SAAN 4855,1805 r90 top
J29 "22284043" Molex_0022284043 4850,850 r270 top
LOGO4 "DANGER HIGH VOLTAGE" IEC_HighVoltage_Medium 975,3350 r180 bottom
LOGO5 "DANGER HIGH VOLTAGE" IEC_HighVoltage_Medium 2350,3350 r0 top locked
Logo8 "FCC disclaimer" FCC_disclaimer 900,75 r0 top
Logo9 "WEEE logo" WEEE_Minimum 1495.16,414.26 r0 top
Logo10 "CAUTION.  READ USER GUIDE BEFORE USE" IEC_Caution_Medium 2370,2575 r0 top
NT1 "Net-Tie" Net-Tie_10milWide_30milLong 65,670 r0 top net-tie
NT2 "Net-Tie" Net-Tie_50milWide_30milLong 495,3840 r180 top net-tie
NT3 "Net-Tie" Net-Tie_10mil 3450,445 r0 bottom net-tie
NT4 "Net-Tie" Net-Tie_10mil 4195,680 r0 top net-tie
NT5 "Net-Tie" Net-Tie_0805_HV_NoOverlay 4630,2210 r90 top net-tie
Q1 "FCX495TA" SOT-89-3 1366.65,2095 r90 top value="150 V"
Q2 "SI2325DS-T1-E3" SOT-23 1145,3690 r180 top value=-150V
Q3 "BSZ900N15NS3 G" PG-TSDSON-8 1055,3900 r0 top value=150V
Q4 "MMBT5401LT1G" SOT-23 720,2790 r90 bottom value="150 V"
Q5 "SI2325DS-T1-E3" SOT-23 960,2995 r180 top value=-150V
Q6 "SI2325DS-T1-E3" SOT-23 1660,3065 r270 top value=-150V
Q7 "BSC160N15NS5ATMA1" PG-TDSON-8 1876.57,3200 r180 top value=150V
Q8 "BSC160N15NS5ATMA1" PG-TDSON-8 1045,3200 r0 top value=150V
Q9 "BSC160N15NS5ATMA1" PG-TDSON-8 1876.57,3500 r180 top value=150V
Q10 "MOSFET_N_D3G1S2" SOT-323 2215,3365 r90 bottom value=60V
Q11 "MMBT5401LT1G" SOT-23 720,2270 r90 bottom value="150 V"
Q12 "SI7898DP-E3" PowerPAK_SO-8 555,3370 r180 top value=150V
Q13 "MMBT5401LT1G" SOT-23 720,1770 r90 bottom value="150 V"
R1 "Resistor" 0603 3065,1560 r270 top value=100
R2 "CRCW120620R0FKEA" 1206 3115,1675 r180 top value=20.0
R3 "CRCW120620R0FKEA" 1206 3115,1770 r180 top value=20.0
R4 "CRCW120620R0FKEA" 1206 3115,1865 r180 top value=20.0
R5 "CRCW2512220RJNEG" 2512 1465,2900 r90 top value=220
R6 "CRCW2512220RJNEG" 2512 1300,2900 r90 top value=220
R7 "CRCW120620R0FKEA" 1206 3065,2010 r270 top value=20.0
R8 "CRCW120620R0FKEA" 1206 2970,2010 r270 top value=20.0
R9 "CRCW2512220RJNEG" 2512 1465,2475 r90 top value=220
R10 "CRCW2512220RJNEG" 2512 1300,2475 r90 top value=220
R11 "CRCW120620R0FKEA" 1206 2875,2010 r270 top value=20.0
R12 "CRCW120620R0FKEA" 1206 2780,2010 r270 top value=20.0
R13 "CRCW120620R0FKEA" 1206 2685,2010 r270 top value=20.0
R14 "CRCW120620R0FKEA" 1206 2590,2010 r270 top value=20.0
R15 "CRCW06030000Z0EA" 0603 2795,1345 r0 bottom value=0
R16 "CRCW120620R0FKEA" 1206 2495,2010 r270 top value=20.0
R17 "CRCW120620R0FKEA" 1206 2400,2010 r270 top value=20.0
R18 "CRCW120620R0FKEA" 1206 2305,2010 r270 top value=20.0
R19 "CRCW120620R0FKEA" 1206 2205,2010 r270 top value=20.0
R20 "CRCW060310K0JNEA" 0603 2375,275 r270 bottom value=10k
R21 "CRCW120620R0FKEA" 1206 2055,1960 r0 top value=20.0
R22 "CRCW120620R0FKEA" 1206 2055,1865 r0 top value=20.0
R23 "CRCW120620R0FKEA" 1206 2055,1770 r0 top value=20.0
R24 "CRCW120620R0FKEA" 1206 2055,1675 r0 top value=20.0
R25 "CRCW060310K0JNEA" 0603 2425,815 r90 bottom value=10k
R26 "CRCW0603100KJNEA" 0603 2625.01,815.01 r90 bottom value=100k
R27 "Resistor" 0603 2035,1445 r0 top value=100
R28 "Resistor" 0603 2035,1525 r0 top value=100
R29 "CRCW060310K0JNEA" 0603 2175,810.87 r90 bottom value=10k
R30 "Resistor" 1210M 1860,1485 r270 top value=0.001
R31 "Resistor" 0603 265,3600 r270 top value=100
R32 "Resistor" 0603 250,3220 r0 bottom value=1.0k
R33 "CRCW25124K70JNEG" 2512 925,3745 r0 top value=4.7k
R34 "Resistor" 0603 250,3085 r0 bottom value=1.0k
R35 "Resistor" 0603 1260,3690 r270 top value=10Meg
R36 "Resistor" 0603 250,2945 r0 bottom value=1.0k
R37 "Resistor" 0603 250,2805 r0 bottom value=1.0k
R38 "CRCW060320K0JNEA" 0603 775,2670 r0 bottom value=20k
R39 "CRCW25124K70JNEG" 2512 795,3125 r270 top value=4.7k
R40 "CRCW25124K70JNEG" 2512 1890,2975 r0 top value=4.7k
R41 "Resistor" 0603 775,2080 r180 bottom value=100
R42 "Resistor" 0603 1570,3080 r270 top value=10Meg
R43 "Resistor" 0603 1080,2980 r270 top value=10Meg
R44 "RC0603FR-0795K3L" 0603 820,2875 r90 bottom value=95.3k
R45 "CRCW12067K50JNEA" 1206 315,3465 r0 top value=7.5k
R46 "Resistor" 2512_WIDE_VISHAY 980,3485 r0 top value=0
R47 "Resistor" 0603 250,2670 r0 bottom value=1.0k
R48 "CRCW12067K50JNEA" 1206 315,3370 r180 top value=7.5k
R49 "Resistor" 0603 250,2530 r0 bottom value=1.0k
R50 "Resistor" 0603 920,3755 r0 bottom value=10Meg
R51 "Resistor" 0603 2215,3545 r0 bottom value=10Meg
R52 "Resistor" 0603 2215,3270 r0 bottom value=10Meg
R53 "Resistor" 0603 250,2270 r0 bottom value=1.0k
R54 "Resistor" 0603 250,2135 r0 bottom value=1.0k
R55 "CRCW060351R0JNEA" 0603 2090,3325 r0 bottom value=51
R56 "CRCW06030000Z0EA" 0603 2090,3610 r0 bottom value=0
R57 "Resistor" 0603 2405,3231.51 r90 bottom value=10k
R58 "CRCW060320K0JNEA" 0603 775,2150 r0 bottom value=20k
R59 "Resistor" 0603 760,2655 r0 top value=5.1k
R60 "RC0603JR-0762KL" 0603 725,2420 r90 bottom value=62k
R61 "CRCW06035K10JNEA" 0603 2740,2765 r270 bottom value=5.1k
R62 "CRCW06035K10JNEA" 0603 3080,2885 r180 bottom value=5.1k
R63 "CRCW06035K10JNEA" 0603 2990,2800 r180 bottom value=5.1k
R64 "CRCW12065K10JNEA" 1206 2910,3255 r270 bottom value=5.1k
R65 "CRCW06037K50JNEA" 0603 2940,3130 r180 bottom value=7.5k
R66 "Resistor" 0603 760,2710 r180 top value=20k
R67 "Resistor" 0603 775,1580 r180 bottom value=100
R68 "CRCW12065K10JNEA" 1206 3005,3255 r90 bottom value=5.1k
R69 "Resistor" 0603 250,1995 r0 bottom value=1.0k
R70 "CRCW12065K10JNEA" 1206 2955,3410 r0 bottom value=5.1k
R71 "CRCW12065K10JNEA" 1206 2765,3410 r0 bottom value=5.1k
R72 "Resistor" 0603 250,1855 r0 bottom value=1.0k
R73 "CRCW12065K10JNEA" 1206 2915,3555 r270 bottom value=5.1k
R74 "CRCW12065K10JNEA" 1206 2855,3700 r0 bottom value=5.1k
R75 "Resistor" 0603 250,1720 r0 bottom value=1.0k
R76 "CRCW12065K10JNEA" 1206 2770,3090 r0 bottom value=5.1k
R77 "CRCW12065K10JNEA" 1206 2655,2995 r0 bottom value=5.1k
R78 "Resistor" 0603 250,1465 r0 bottom value=1.0k
R79 "CRCW060320K0JNEA" 0603 775,1650 r0 bottom value=20k
R80 "CRCW060327K0JNEA" 0603 870,1820 r0 bottom value=27k
R81 "Resistor" 0603 775,1075 r180 bottom value=100
R82 "Resistor" 0603 715,1225 r0 bottom value=5.1k
R83 "Resistor" 0603 250,1325 r0 bottom value=1.0k
R84 "Resistor" 0603 250,1190 r0 bottom value=1.0k
R85 "Resistor" 0603 250,1050 r0 bottom value=1.0k
R86 "Resistor" 0603 250,910 r0 bottom value=1.0k
R87 "CRCW1206200RFKEA" 1206 1195,2625 r90 bottom value=200
R88 "CRCW1206200RFKEA" 1206 1295,2525 r90 bottom value=200
R89 "CRCW060310K0JNEA" 0603 2675,1130.87 r90 bottom value=10k
R90 "CRCW1206200RFKEA" 1206 1195,2425 r90 bottom value=200
R91 "CRCW0603100KJNEA" 0603 2875,1130.87 r90 bottom value=100k
R92 "CRCW060310K0JNEA" 0603 3830,2340 r180 bottom value=10k
R93 "CRCW1206200RFKEA" 1206 1295,2325 r90 bottom value=200
R94 "CRCW060310K0JNEA" 0603 3830,2140 r180 bottom value=10k
R95 "CRCW1206200RFKEA" 1206 1195,2225 r90 bottom value=200
R96 "CRCW1206200RFKEA" 1206 1295,2065 r90 bottom value=200
R97 "CRCW060310K0JNEA" 0603 3830,1940 r180 bottom value=10k
R98 "CRCW1206200RFKEA" 1206 1195,1900 r90 bottom value=200
R99 "CRCW060310K0JNEA" 0603 3830,1740 r180 bottom value=10k
R100 "CRCW1206200RFKEA" 1206 1295,1800 r90 bottom value=200
R101 "CRCW1206200RFKEA" 1206 1195,1700 r90 bottom value=200
R102 "CRCW1206200RFKEA" 1206 1295,1600 r90 bottom value=200
R103 "CRCW1206200RFKEA" 1206 1195,1500 r90 bottom value=200
R104 "CRCW1206200RFKEA" 1206 1295,1400 r90 bottom value=200
R105 "CRCW1206200RFKEA" 1206 1195,1300 r90 bottom value=200
R106 "CRCW1206200RFKEA" 1206 1295,1200 r90 bottom value=200
R107 "CRCW1206200RFKEA" 1206 1195,1100 r90 bottom value=200
R108 "CRCW1206200RFKEA" 1206 1295,1000 r90 bottom value=200
R109 "CRCW060310K0JNEA" 0603 3655,405 r90 bottom value=10k
R110 "CRCW060310K0JNEA" 0603 3600,405 r90 bottom value=10k
R111 "CRCW060310K0JNEA" 0603 3300,405 r90 bottom value=10k
R112 "CRCW06030000Z0EA" 0603 3990,1650 r180 top value=0
R113 "CRCW06030000Z0EA" 0603 4180,1631 r0 top value=0
R114 "Resistor" 0402 4170,290 r90 top value=33
R115 "Resistor" 0402 4215,290 r90 top value=33
R116 "Resistor" 0402 4260,290 r270 top value=2.0k
R117 "Resistor" 0402 4280,220 r0 top value=10k
R118 "Resistor" 0402 4335,265 r180 top value=1.0Meg
R119 "Resistor" 0402 4335,310 r0 top value=1.0Meg
R120 "Resistor" 0402 3340,265 r90 top value=330
R121 "Resistor" 0402 3455,265 r90 top value=330
R122 "Resistor" 0402 3570,265 r90 top value=330
R123 "Resistor" 0402 4720,925 r90 top value=10k
RT1 "Thermistor" THERMISTOR_103AT-2 2105,1295 r180 top value=10k
RT2 "Thermistor" THERMISTOR_103AT-2 2105,1160 r180 top value=10k
S1 "SW_KST221JLFS" SW_KST221JLFS 2315,225 r0 top
S2 "SW_KST221JLFS" SW_KST221JLFS 1840,225 r180 top
S3 "PTS820 J20M SMTR LFS" SW_PTS820 4800,1175 r180 top
SH-J1 "SNT-100-BK-G" SNT-100-BK-G 1050,1550 r180 top value=1x2
SH-J2 "SNT-100-BK-G" SNT-100-BK-G 1050,1450 r180 top value=1x2
SH-J3 "SNT-100-BK-G" SNT-100-BK-G 1050,1350 r180 top value=1x2
SH-J4 "SNT-100-BK-G" SNT-100-BK-G 1050,1250 r180 top value=1x2
SH-J5 "SNT-100-BK-G" SNT-100-BK-G 1050,1150 r180 top value=1x2
SH-J6 "SNT-100-BK-G" SNT-100-BK-G 1050.01,1050.01 r180 top value=1x2
SH-J7 "SNT-100-BK-G" SNT-100-BK-G 1050,2675 r180 top value=1x2
SH-J8 "SNT-100-BK-G" SNT-100-BK-G 1050,2575 r180 top value=1x2
SH-J9 "SNT-100-BK-G" SNT-100-BK-G 1050,2475 r180 top value=1x2
SH-J10 "SNT-100-BK-G" SNT-100-BK-G 1050,2375 r180 top value=1x2
SH-J11 "SNT-100-BK-G" SNT-100-BK-G 1050,2275 r180 top value=1x2
SH-J12 "SNT-100-BK-G" SNT-100-BK-G 1050,2175 r180 top value=1x2
SH-J13 "SNT-100-BK-G" SNT-100-BK-G 2025,740 r180 top value=1x2
SH-J14 "SNT-100-BK-G" SNT-100-BK-G 2575,745 r180 top value=1x2
SH-J15 "SNT-100-BK-G" SNT-100-BK-G 2825,1060 r180 top value=1x2
SH-J16 "SNT-100-BK-G" SNT-100-BK-G 3745,2820 r90 top value=1x2
SH-J17 "SNT-100-BK-G" SNT-100-BK-G 3745,3220 r90 top value=1x2
SH-J18 "SNT-100-BK-G" SNT-100-BK-G 1050,1950 r180 top value=1x2
SH-J19 "SNT-100-BK-G" SNT-100-BK-G 1050,1850 r180 top value=1x2
SH-J20 "SNT-100-BK-G" SNT-100-BK-G 1050,1750 r180 top value=1x2
SH-J21 "SNT-100-BK-G" SNT-100-BK-G 1050,1650 r180 top value=1x2
TP1 "TESTPOINT" Keystone5010 145,3425 r0 top
TP2 "TESTPOINT" TP_VIA_060RND040 3235,1590 r0 top
TP3 "TESTPOINT" TP_VIA_060RND040 3090,1450 r0 top
TP4 "TESTPOINT" TP_VIA_060RND040 3090,1320 r0 top
TP5 "TESTPOINT" TP_VIA_060RND040 3300,1326.26 r0 top
TP6 "TESTPOINT" TP_VIA_060RND040 2440,510 r0 top
TP7 "TESTPOINT" TP_VIA_060RND040 2245,1295 r0 top
TP8 "TESTPOINT" TP_VIA_060RND040 2245,1160 r90 top
TP9 "TESTPOINT" Keystone5011 145,575 r0 top
TP10 "TESTPOINT" TP_50MIL-25MILHOLE 2350,1055 r90 top
TP11 "TESTPOINT" TP_50MIL-25MILHOLE 1995,510 r0 top
TP12 "TESTPOINT" TP_50MIL-25MILHOLE 2185,1445 r90 top
TP13 "TESTPOINT" TP_50MIL-25MILHOLE 2185,1525 r90 top
TP14 "5006" Keystone5006 750,950 r0 top
TP15 "5006" Keystone5006 640,3130 r0 top
TP16 "5006" Keystone5006 3300,3500 r0 top
TP17 "5006" Keystone5006 1825,510 r0 top
TP18 "TESTPOINT" TP_VIA_060RND040 3300,1450 r90 top
TP19 "TESTPOINT" TP_VIA_060RND040 1700,1425 r90 top
TP20 "TESTPOINT" TP_VIA_060RND040 1210,3855 r90 top
TP21 "TESTPOINT" TP_VIA_060RND040 785,3525 r90 top
TP22 "TESTPOINT" TP_VIA_060RND040 2135,3045 r90 top
TP23 "TESTPOINT" TP_VIA_060RND040 1290,3555 r90 top
TP24 "TESTPOINT" TP_VIA_060RND040 375,3275 r90 top
TP25 "TESTPOINT" TP_VIA_060RND040 1700,2690 r90 top
TP26 "TESTPOINT" TP_VIA_060RND040 1050,2875 r90 top
TP27 "TESTPOINT" TP_VIA_060RND040 1700,2850 r90 top
TP28 "TESTPOINT" TP_VIA_060RND040 2815,3200 r90 top
TP29 "TESTPOINT" TP_VIA_060RND040 745,2930 r90 top
TP30 "TESTPOINT" TP_VIA_060RND040 2815,2800 r90 top
TP31 "TESTPOINT" TP_VIA_060RND040 3095,3000 r90 top
TP32 "TESTPOINT" TP_VIA_060RND040 3095,2800 r90 top
TP33 "TESTPOINT" TP_VIA_060RND040 3095,3410 r90 top
TP34 "TESTPOINT" TP_VIA_060RND040 2815,3000 r90 top
TP35 "TESTPOINT" TP_VIA_060RND040 3095,3200 r90 top
TP36 "TESTPOINT" TP_VIA_060RND040 1700,1545 r90 top
TP37 "TESTPOINT" TP_50MIL-25MILHOLE 3570,2470 r90 top
TP38 "TESTPOINT" TP_50MIL-25MILHOLE 3570,2270 r90 top
TP39 "TESTPOINT" TP_50MIL-25MILHOLE 3570,2070 r90 top
TP40 "TESTPOINT" TP_50MIL-25MILHOLE 3570,1870 r90 top
TP41 "TESTPOINT" TP_50MIL-25MILHOLE 2455,1055 r90 top
TP42 "TESTPOINT" TP_50MIL-25MILHOLE 4125,1500 r90 top
TP43 "5005" Keystone5005 4055,300 r0 top value=Red
TP44 "5005" Keystone5005 3705,100 r0 top value=Red
TP45 "TESTPOINT" TP_SM_1MM 4720,710 r90 top
U1 "bq76952PFBT" PFB0048A_N 2600,1500 r270 top locked
U2 "BQ771807DPJR" DPJ0008A 575,2670 r90 bottom
U3 "BQ771807DPJR" DPJ0008A 575,2150 r90 bottom
U4 "BQ771807DPJR" DPJ0008A 575,1650 r90 bottom
U5 "BQ771807DPJR" DPJ0008A 575,1150 r90 bottom
U6 "TPD1E10B06DPYR" DPY0002A#1 4137,3785 r180 bottom
U7 "TPD1E10B06DPYR" DPY0002A#1 4655,3142 r270 bottom
U8 "TPD1E10B06DPYR" DPY0002A#1 4437,3785 r180 bottom
U9 "TPD1E10B06DPYR" DPY0002A#1 4655,3268 r90 bottom
U10 "SN74LVC2T45DCTR" DCT0008A_N 4135,1741 r0 top
U11 "CMP-0038965-1" PN0080A_N 4145,1000 r270 top
U12 "TPD1E10B06DPYT" DPY0002A#1 4180,160 r90 bottom
U13 "TPD1E10B06DPYT" DPY0002A#1 4225,160 r90 bottom
U14 "CMP-0035539-1" DBV0005A_N 3755,385 r180 top
U15 "TPD1E10B06DPYT" DPY0002A#2 4770,787 r270 top
U16 "TPD1E10B06DPYT" DPY0002A#2 4740,850 r0 top
Y1 "CSTCR4M00G55B-R0" Murata_CSTCR_G 4540,980 r90 top
ZZ1 "These assemblies are ESD sensitive, ESD precautions shall be observed." AssemblyNote 200,4400 r0 top
ZZ2 "These assemblies must be clean and free from flux and all contaminants. Use of no clean flux is not acceptable." AssemblyNote 200,4300 r0 top
ZZ3 "These assemblies must comply with workmanship standards IPC-A-610 Class 2, unless otherwise specified." AssemblyNote 200,4200 r0 top

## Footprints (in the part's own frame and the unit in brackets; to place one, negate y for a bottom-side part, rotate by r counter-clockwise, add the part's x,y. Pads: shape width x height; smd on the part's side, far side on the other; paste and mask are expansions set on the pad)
0402 [mm] "0402 from SM-752 data"
  rect 0.8x0.6 smd: 1(-0.6,0) 2(0.6,0)
  silkscreen extent -1.22,-0.52 1.22,0.52, body extent -0.55,-0.3 0.55,0.3, height 0.6
0603 [mm] "0603 from SM-752 data"
  rect 1x0.95 smd: 1(-0.8,0) 2(0.8,0)
  silkscreen extent -1.52,-0.69 1.52,0.69, body extent -0.87,-0.47 0.87,0.47, height 1
0603S [mil]
  rect 20x35 smd: 1(-30,0) 2(30,0)
  body extent -34,-19 34,19, height 39
0805_HV [mil] "0805 with 30mil clearance between pads"
  rect 50x63 smd: 1(-40,0) 2(40,0)
  silkscreen extent -74,-40 74,40, body extent -43,-29 43,29, height 57
1206 [mm] "1206 from SM-752 data"
  rect 1.3x1.85 smd: 1(-1.45,0) 2(1.45,0)
  silkscreen extent -2.4,-1.21 2.4,1.21, body extent -1.7,-0.9 1.7,0.9, height 1.35
1206_180 [mm] "1206_180"
  rect 1.1x1.6 smd: 1(-1.7,0) 2(1.7,0)
  silkscreen extent -0.9,-1 0.9,1, body extent -1.75,-0.95 1.75,0.95, height 1.8
1210M [mm] "1210 from SM-752 data"
  rect 1.5x2.8 smd: 1(-1.55,0) 2(1.55,0)
  silkscreen extent -2.75,-1.85 2.75,1.85, body extent -1.7,-1.35 1.7,1.35, height 1.35
2512 [mm] "Chip Resistor, Body 6.3x3.2mm, IPC Medium Density"
  rect 1.3x3.4 smd: 1(-2.95,0) 2(2.95,0)
  silkscreen extent -1.9,-1.6 1.9,1.6, body extent -3.22,-1.67 3.22,1.67, height 0.71
2512_WIDE_VISHAY [mm] "Vishay recommended land pattern"
  rect 1.9x7.6 smd: 1(-1.55,0) 2(1.55,0)
  silkscreen extent -0.3,-3.32 0.3,3.35, body extent -1.7,-3.25 1.7,3.25, height 0.9
AssemblyNote [mil] "Assembly Note"
Bumpon_SJ5003Transparent [mil] "3M Hemispherical Bumpon transparent"
  round 1 on Mech4: 0(0,0)
  silkscreen extent -228,-228 228,228, body extent -219,-219 219,219, height 197
CONN_22-05-3041 [mm] "MOLEX"
  rect 1.65x1.65 hole 1.02: 1(-3.81,5.7)
  round 1.65 hole 1.02: 2(-1.27,5.7) 3(1.27,5.7) 4(3.81,5.7)
  silkscreen extent -5,0 5,4.18, body extent -5,-6.91 5,6.02, height 6.37
CONN_PEC02SAAN [mm] "SULLINS"
  rrect7% 1.5x1.5 hole 1.016: 1(-1.27,0)
  round 1.5 hole 1.016: 2(1.27,0)
  silkscreen extent -2.54,-1.52 2.54,1.27, body extent -2.54,-1.27 2.54,1.27, height 8.38
CONN_PEC06DAAN [mm] "SULLINS"
  rect 1.65x1.65 hole 1.016 mask+0: 1(-6.35,-1.27)
  round 1.65 hole 1.016 mask+0: 2(-6.35,1.27) 3(-3.81,-1.27) 4(-3.81,1.27) 5(-1.27,-1.27) 6(-1.27,1.27) 7(1.27,-1.27) 8(1.27,1.27) 9(3.81,-1.27) 10(3.81,1.27) 11(6.35,-1.27) 12(6.35,1.27)
  silkscreen extent -8.72,-2.6 7.62,2.54, body extent -7.62,-2.54 7.62,2.54, height 8.38
DBV0005A_N [mm] "SOT23, 5-Leads, Body 2.9x1.6mm, Pitch 0.95mm, Lead Span 2.8mm, IPC Medium Density"
  rrect17% 1x0.6 smd: 1(-1.375,0.95) 2(-1.375,0) 3(-1.375,-0.95) 4(1.375,-0.95) 5(1.375,0.95)
  silkscreen extent -0.25,-1.55 0.25,1.55, body extent -1.42,-1.46 1.42,1.46, height 1.09
DCT0008A_N [mm] "TSOP, 8-Leads, Body 3x2.8mm, Pitch 0.65mm, IPC Medium Density"
  oval 1.05x0.4 smd: 1(-1.975,0.975) 2(-1.975,0.325) 3(-1.975,-0.325) 4(-1.975,-0.975) 5(1.975,-0.975) 6(1.975,-0.325) 7(1.975,0.325) 8(1.975,0.975)
  silkscreen extent -2.32,-1.57 0.6,1.58, body extent -2.01,-1.47 2.01,1.48, height 1.3
DPJ0008A [mm]
  oval 0.7x0.25 smd: 1(-1.85,0.95) 2(-1.85,0.325) 3(-1.85,-0.325) 4(-1.85,-0.975) 5(1.85,-0.975) 6(1.85,-0.325) 7(1.85,0.325) 8(1.85,0.95)
  rect 2.4x2.4 smd paste-1.2: 9(0,0)
  silkscreen extent -2.15,-1.65 2.15,1.65, body extent -2.05,-1.55 2.05,1.55, height 0.81
DPY0002A#1 [mm] "X1SON-2"
  rrect57% 0.35x0.6 smd paste-0.5 mask-0.05: 1(-0.325,0) 2(0.325,0)
  rrect33% 0.3x0.5 on Bottom Paste: 1S(-0.35,0) 2S(0.35,0)
  body extent -0.5,-0.3 0.5,0.3, height 0.45
DPY0002A#2 [mm] "X1SON-2"
  rrect57% 0.35x0.6 smd paste-0.5 mask-0.05: 1(-0.325,0) 2(0.325,0)
  rrect33% 0.3x0.5 on Top Paste: 1S(-0.35,0) 2S(0.35,0)
  body extent -0.5,-0.3 0.5,0.3, height 0.45
FCC_disclaimer [mil]
Fiducial10-20 [mm]
  round 1 smd mask+0.5: 1(0,0)
  Layer 1 - Top Layer keep-out circle w1.178: c0,0 r0.5
FP-OSTTE040161_HDR4-MFG [mm]
  rrect6% 1.7x1.7 hole 1.1 paste-1000 mask+0: 1(-5.25,0.1)
  round 1.7 hole 1.1 paste-1000 mask+0: 2(-1.75,0.1) 3(1.75,0.1) 4(5.25,0.1)
  body extent -7.68,-3.75 7.68,3.75, height 0.25
FP-OSTTE050161_HDR5-MFG [mm]
  rrect6% 1.7x1.7 hole 1.1 paste-1000 mask+0: 1(-7,0.1)
  round 1.7 hole 1.1 paste-1000 mask+0: 2(-3.5,0.1) 3(0,0.1) 4(3.5,0.1) 5(7,0.1)
  body extent -9.43,-3.75 9.43,3.75, height 0.25
FP-OSTTE060161_HDR6-MFG [mm]
  rrect6% 1.7x1.7 hole 1.1 paste-1000 mask+0: 1(-8.75,0.1)
  round 1.7 hole 1.1 paste-1000 mask+0: 2(-5.25,0.1) 3(-1.75,0.1) 4(1.75,0.1) 5(5.25,0.1) 6(8.75,0.1)
  body extent -11.17,-3.75 11.17,3.75, height 0.25
FUSE_SFK-xx30x [mm] "Fuse"
  rect 7.4x1.2 smd paste+0 mask+0.07: 1(0,2.05) 3(0,-2.05)
  rect 0.75x3 smd paste+0 mask+0.07: 2(-5.575,0)
  Layer 1 - Top Layer region: -5.2,1.5 -5.2,-1.5 -3.8,-0.35 -3.8,0.35
  silkscreen extent -4.75,-2.5 4.75,2.5, body extent -4.75,-2.5 4.75,2.5, height 2
IEC_Caution_Medium [mil]
  silkscreen extent -217,-182 217,193
IEC_HighVoltage_Medium [mil]
  silkscreen extent -217,-176 217,200
Keystone5005 [mil] "Keystone Compact loops"
  round 87 hole 63: 1(0,0)
  silkscreen extent -70,-70 70,70, body extent -63,-63 62,63, height 225
Keystone5006 [mil] "Keystone Compact loops"
  round 87 hole 63: 1(0,0)
  silkscreen extent -70,-70 70,70, body extent -63,-63 62,63, height 225
Keystone5010 [mil] "Keystone Multipurpose loops"
  round 87 hole 63: 1(0,0)
  silkscreen extent -70,-70 70,70, body extent -63,-63 63,62, height 319
Keystone5011 [mil] "Keystone Multipurpose loops"
  round 87 hole 63: 1(0,0)
  silkscreen extent -70,-70 70,70, body extent -63,-63 63,62, height 319
Molex_47346-1001 [mm] "Receptacle, 0.65mm, 5x1, R/A, SMT"
  rect 0.45x1.38 smd: 1(-1.3,4.11) 2(-0.65,4.11) 3(0,4.11) 4(0.65,4.11) 5(1.3,4.11)
  rect 1.475x2.1 smd: 6(-2.462,3.75) 7(2.462,3.75)
  rect 2.375x1.95 smd: 8(-2.913,1.45) 11(2.913,1.45)
  rect 1.175x1.95 smd: 9(-0.837,1.45) 10(0.837,1.45)
  silkscreen extent -3.75,2.83 3.75,5.67, body extent -3.9,-0.7 3.9,4.3, height 2.68
Molex_87898-0304 [mm] "Header, 2.54mm, 3x1, SMT"
  rrect8% 1.27x2.96 smd: 1(-2.54,1.8) 2(0,-1.8) 3(2.54,1.8)
  silkscreen extent -4.1,-1.26 3.81,1.25, body extent -3.81,-2.4 3.81,2.4, height 9.65
Molex_0022284043 [mm] "Header, 2.54mm, 4x1, TH"
  rect 1.55x1.55 hole 1.02: 1(-3.81,0)
  round 1.55 hole 1.02: 2(-1.27,0) 3(1.27,0) 4(3.81,0)
  silkscreen extent -5.08,-1.24 5.08,1.5, body extent -5.08,-1.24 5.08,1.24, height 8.4
Murata_CSTCR_G [mm] "Murata"
  rect 0.4x2.6 smd: 1(-1.5,0) 2(0,0) 3(1.5,0)
  Layer 1 - Top Layer region: -0.4,0.8 0.4,0.8 0.4,1.3 -0.4,1.3
  Layer 1 - Top Layer region: -0.4,-1.301 -0.4,-0.801 0.4,-0.801 0.4,-1.301
  Layer 1 - Top Layer region: -1.9,0.8 -1.1,0.8 -1.1,1.3 -1.9,1.3
  Layer 1 - Top Layer region: -1.9,-1.301 -1.9,-0.801 -1.1,-0.801 -1.1,-1.301
  Layer 1 - Top Layer region: 1.1,0.8 1.9,0.8 1.9,1.3 1.1,1.3
  Layer 1 - Top Layer region: 1.1,-1.301 1.1,-0.801 1.9,-0.801 1.9,-1.301
  body extent -2.25,-1 2.25,1, height 1.16
Net-Tie_10mil [mil] "10mil net tie, no solder mask opening, no solder paste"
  rect 10x10 smd paste-5 mask-5: 1(-10,0) 2(10,0)
  Layer 1 - Top Layer region: -6,5 6,5 6,-5 -6,-5
Net-Tie_10milWide_30milLong [mil] "10mil net tie, no solder mask opening, no solder paste"
  rect 30x10 smd paste-5 mask-5: 1(-15,0) 2(15,0)
Net-Tie_50milWide_30milLong [mil] "50mil net tie, no solder mask opening, no solder paste"
  rect 30x200 smd paste-20 mask-20: 1(-15,0) 2(15,0)
Net-Tie_0805_HV_NoOverlay [mil] "0805_HV pads tied by 10mil copper trace which can be cut.  An 0805 part can be placed on pads."
  rect 50x63 smd paste-25: 1(-40,0) 2(40,0)
  Layer 1 - Top Layer lines w10: -16,0 16,0
  Layer 1 - Top Layer keep-out lines w1: -22,30.91 -22,-30.91 ; -14.96,30.91 14.96,30.91 ; 22,30.91 22,-30.91 ; -14.96,-30.91 14.96,-30.91
PFB0048A_N [mm] "Thin QFP, 48-Leads, Body 7x7mm, Pitch 0.5mm, IPC Medium Density"
  oval 1.45x0.3 smd: 1(-4.225,2.75) 2(-4.225,2.25) 3(-4.225,1.75) 4(-4.225,1.25) 5(-4.225,0.75) 6(-4.225,0.25) 7(-4.225,-0.25) 8(-4.225,-0.75) 9(-4.225,-1.25) 10(-4.225,-1.75) 11(-4.225,-2.25) 12(-4.225,-2.75) 25(4.225,-2.75) 26(4.225,-2.25) 27(4.225,-1.75) 28(4.225,-1.25) 29(4.225,-0.75) 30(4.225,-0.25) 31(4.225,0.25) 32(4.225,0.75) 33(4.225,1.25) 34(4.225,1.75) 35(4.225,2.25) 36(4.225,2.75)
  oval 0.3x1.45 smd: 13(-2.75,-4.225) 14(-2.25,-4.225) 15(-1.75,-4.225) 16(-1.25,-4.225) 17(-0.75,-4.225) 18(-0.25,-4.225) 19(0.25,-4.225) 20(0.75,-4.225) 21(1.25,-4.225) 22(1.75,-4.225) 23(2.25,-4.225) 24(2.75,-4.225) 37(2.75,4.225) 38(2.25,4.225) 39(1.75,4.225) 40(1.25,4.225) 41(0.75,4.225) 42(0.25,4.225) 43(-0.25,4.225) 44(-0.75,4.225) 45(-1.25,4.225) 46(-1.75,4.225) 47(-2.25,4.225) 48(-2.75,4.225)
  silkscreen extent -4.17,-2.75 2.75,3.58, body extent -4.5,-4.5 4.5,4.5, height 1.07
PG-TDSON-8 [mm] "Infineon recommended land pattern"
  rect 1.2x0.65 smd: 1(-2.825,1.905) 2(-2.825,0.635) 3(-2.825,-0.635) 4(-2.825,-1.905)
  rect 0.5x0.7 smd: 5(3.175,-2) 6(3.175,-0.675) 7(3.175,0.675) 8(3.175,2)
  rect 4.5x4.7 smd paste-2.25: 9(0.675,0)
  silkscreen extent -3.74,-3 3.74,3, body extent -3.18,-2.89 3.18,2.9, height 1.1
PG-TSDSON-8 [mm] "Infineon recommended land pattern"
  rect 0.8x0.34 smd: 1(-1.538,0.975) 2(-1.538,0.325) 3(-1.538,-0.325) 4(-1.538,-0.975)
  rect 0.65x0.34 smd: 5(1.538,-0.975) 6(1.538,-0.325) 7(1.538,0.325) 8(1.538,0.975)
  rect 1.71x2.29 smd: 9(0.358,0)
  silkscreen extent -2.22,-1.8 2.22,1.8, body extent -1.7,-1.7 1.7,1.7, height 1.1
PN0080A_N [mm] "QFP, 80-Leads, Body 12x12mm, Pitch 0.5mm, IPC Medium Density"
  oval 1.45x0.3 smd: 1(-6.725,4.75) 2(-6.725,4.25) 3(-6.725,3.75) 4(-6.725,3.25) 5(-6.725,2.75) 6(-6.725,2.25) 7(-6.725,1.75) 8(-6.725,1.25) 9(-6.725,0.75) 10(-6.725,0.25) 11(-6.725,-0.25) 12(-6.725,-0.75) 13(-6.725,-1.25) 14(-6.725,-1.75) 15(-6.725,-2.25) 16(-6.725,-2.75) 17(-6.725,-3.25) 18(-6.725,-3.75) 19(-6.725,-4.25) 20(-6.725,-4.75) 41(6.725,-4.75) 42(6.725,-4.25) 43(6.725,-3.75) 44(6.725,-3.25) 45(6.725,-2.75) 46(6.725,-2.25) 47(6.725,-1.75) 48(6.725,-1.25) 49(6.725,-0.75) 50(6.725,-0.25) 51(6.725,0.25) 52(6.725,0.75) 53(6.725,1.25) 54(6.725,1.75) 55(6.725,2.25) 56(6.725,2.75) 57(6.725,3.25) 58(6.725,3.75) 59(6.725,4.25) 60(6.725,4.75)
  oval 0.3x1.45 smd: 21(-4.75,-6.725) 22(-4.25,-6.725) 23(-3.75,-6.725) 24(-3.25,-6.725) 25(-2.75,-6.725) 26(-2.25,-6.725) 27(-1.75,-6.725) 28(-1.25,-6.725) 29(-0.75,-6.725) 30(-0.25,-6.725) 31(0.25,-6.725) 32(0.75,-6.725) 33(1.25,-6.725) 34(1.75,-6.725) 35(2.25,-6.725) 36(2.75,-6.725) 37(3.25,-6.725) 38(3.75,-6.725) 39(4.25,-6.725) 40(4.75,-6.725) 61(4.75,6.725) 62(4.25,6.725) 63(3.75,6.725) 64(3.25,6.725) 65(2.75,6.725) 66(2.25,6.725) 67(1.75,6.725) 68(1.25,6.725) 69(0.75,6.725) 70(0.25,6.725) 71(-0.25,6.725) 72(-0.75,6.725) 73(-1.25,6.725) 74(-1.75,6.725) 75(-2.25,6.725) 76(-2.75,6.725) 77(-3.25,6.725) 78(-3.75,6.725) 79(-4.25,6.725) 80(-4.75,6.725)
  silkscreen extent -6.85,-5.6 5.6,5.6, body extent -7,-7 7,7, height 1.56
PowerPAK_SO-8 [mil] "Vishay PowerPAK SO-8, Body 5.3x6.0mm (max), Pitch 1.27mm, IPC Medium Density"
  rect 50x24 smd mask+2.99: 1(-109.5,75) 2(-109.5,25) 3(-109.5,-25) 4(-109.5,-75)
  rect 48x24 smd mask+2.99: 5(109.5,-75) 8(109.5,75)
  rect 48x24 smd paste-12 mask+2.99: 6(109.5,-25) 7(109.5,25)
  rect 150x154 smd paste-75 mask+2.99: 9(22.5,0)
  silkscreen extent -130,-104 59,104, body extent -121,-102 121,102, height 43
SNT-100-BK-G [mil] "Samtec STEP model"
  round 1 on Mech3: 0(0,0)
  body extent -100,-50 100,50, height 344
SOD-123 [mm] "On Semi recommended land pattern"
  rect 0.915x1.22 smd: 1(-1.637,0) 2(1.637,0)
  silkscreen extent -2.74,-1.17 2.03,1.17, body extent -1.93,-0.9 1.93,0.9, height 1.35
SOT-23 [mm] "SOT23, 3-Leads, Body 2.9x1.3mm, Pitch 0.95mm, Lead Span 2.5mm, IPC Medium Density"
  rrect50% 1x0.6 smd: 1(-1.2,0.95) 2(-1.2,-0.95) 3(1.2,0)
  silkscreen extent -1.62,-1.5 0.7,1.5, body extent -1.16,-1.45 1.21,1.45, height 1
SOT-89-3 [mm] "SOT, 3-Leads, Body 4.6 x 2.6 mm, Pitch 1.5mm"
  rect 1.4x0.9 smd: 1(-1.9,1.5) 3(-1.9,-1.5)
  rect 1.8x0.9 smd: 2(-1.7,0)
  oct 3.4x1.9 smd: 4(0.9,0)
  silkscreen extent -1.3,-2.45 1.33,2.45, body extent -2.42,-2.28 1.83,2.32, height 1.62
SOT-323 [mm] "Diodes Inc recommended land pattern.  2016-02-24"
  rrect21% 0.6x0.47 smd: 1(-0.95,0.65) 2(-0.95,-0.65) 3(0.95,0)
  silkscreen extent -1.14,-1.22 0.77,1.22, body extent -1.13,-1.13 1.12,1.12, height 1.13
SPARK_GAP2 [mil] "Copied from PADS legacy libraries."
  rect 10x20 smd: 1(0,20) 2(0,-10)
  Layer 1 - Top Layer region: -15,30 -25,30 -25,-30 25,-30 25,30 15,30 15,-20 -15,-20 -15,30
Sullins_PEC06SAAN [mm] "TH, 6-Leads, Body 608x100mil, Pitch 100mil"
  rect 1.5x1.5 hole 1.016: 1(-6.35,0)
  round 1.5 hole 1.016: 2(-3.81,0) 3(-1.27,0) 4(1.27,0) 5(3.81,0) 6(6.35,0)
  silkscreen extent -8.64,-1.27 7.72,1.27, body extent -7.72,-1.27 7.72,1.27, height 8.59
SULLINS_PEC10DAAN [mm] "SULLINS"
  rrect50% 1.55x1.55 hole 1.016: 1(-1.27,11.43)
  round 1.55 hole 1.016: 2(1.27,11.43) 3(-1.27,8.89) 4(1.27,8.89) 5(-1.27,6.35) 6(1.27,6.35) 7(-1.27,3.81) 8(1.27,3.81) 9(-1.27,1.27) 10(1.27,1.27) 11(-1.27,-1.27) 12(1.27,-1.27) 13(-1.27,-3.81) 14(1.27,-3.81) 15(-1.27,-6.35) 16(1.27,-6.35) 17(-1.27,-8.89) 18(1.27,-8.89) 19(-1.27,-11.43) 20(1.27,-11.43)
  silkscreen extent -2.9,-12.7 2.54,12.7, body extent -2.54,-12.7 2.54,12.7, height 8.38
Sullins_PxC05SAAN [mm] "Header, 2.54mm, 5x1, TH"
  rect 1.55x1.55 hole 1.016: 1(-5.08,0)
  round 1.55 hole 1.016: 2(-2.54,0) 3(0,0) 4(2.54,0) 5(5.08,0)
  silkscreen extent -6.35,-1.75 6.35,1.27, body extent -6.35,-1.27 6.35,1.27, height 5.84
Sullins_xxC07SAAN [mm] "Header, 2.54 mm, 7x1, TH"
  rect 1.55x1.55 hole 1.016: 1(-7.62,0)
  round 1.55 hole 1.016: 2(-5.08,0) 3(-2.54,0) 4(0,0) 5(2.54,0) 6(5.08,0) 7(7.62,0)
  silkscreen extent -8.89,-1.27 8.89,1.7, body extent -8.89,-1.27 8.89,1.27, height 8.38
Sullins_xxC11SAAN [mm] "Header, 2.54 mm, 11x1, TH"
  rect 1.55x1.55 hole 1.016: 1(-12.7,0)
  round 1.55 hole 1.016: 2(-10.16,0) 3(-7.62,0) 4(-5.08,0) 5(-2.54,0) 6(0,0) 7(2.54,0) 8(5.08,0) 9(7.62,0) 10(10.16,0) 11(12.7,0)
  silkscreen extent -13.97,-1.27 13.97,1.7, body extent -13.97,-1.27 13.97,1.27, height 8.38
SW_KST221JLFS [mm] "C&K"
  rect 2.8x1 smd: 1(-2.9,2) 2(2.9,2) 3(-2.9,-2) 4(2.9,-2)
  body extent -3.25,-3.25 3.25,3.25, height 5
SW_PTS820 [mm] "SMT, 2-Leads, Body 3.9x2.9mm"
  rect 0.95x1.4 smd: 1(-2.075,0) 2(2.075,0)
  round 0.8 hole 0.8 unplated: MH1(0,0.9) MH2(0,-0.9)
  rect 1.15x0.75 smd: MP1(-1.575,1.525) MP2(1.575,1.525) MP3(1.575,-1.525) MP4(-1.575,-1.525)
  silkscreen extent -2.45,-2.2 2.45,2.2, body extent -2.25,-1.45 2.25,1.45, height 2
TERM_BLK_ED555-2DS [mil]
  rrect4% 100x100 hole 50: 1(0,0)
  round 100 hole 50: 2(138,0)
  silkscreen extent -93,-161 215,113, body extent -69,-150 207,106, height 323
THERMISTOR_103AT-2 [mil] "SEMITEC"
  rect 65x65 hole 35: 1(-50,0)
  round 65 hole 35: 2(50,0)
  body extent -78,-47 79,47, height 338
TP_50MIL-25MILHOLE [mil]
  round 50 hole 25: 1(0,0)
TP_SM_1MM [mm] "1mm Test Point, SMT"
  round 1 smd paste-0.5: 1(0,0)
TP_VIA_060RND040 [mil] "TP_VIA_060RND040"
  round 60 hole 40: 1(0,0)
WEEE_Minimum [mil] "WEEElie bin"
  silkscreen extent -95,-172 99,104
WL-SMCW_GREEN [mm] "WURTH"
  rect 0.8x0.8 smd: 1(-0.8,0) 2(0.8,0)
  silkscreen extent -1.9,-0.8 1.2,0.8, body extent -0.85,-0.45 0.85,0.45, height 0.8
WL-SMCW_RED [mm] "WURTH"
  rect 0.8x0.8 smd: 1(-0.8,0) 2(0.8,0)
  silkscreen extent -1.9,-0.8 1.2,0.8, body extent -0.85,-0.45 0.85,0.45, height 0.8
WURTH_61300211121 [mm] "Header, 2.54mm, 2x1, TH"
  rrect50% 1.65x1.65 hole 1.15: 1(-1.27,0)
  round 1.65 hole 1.15: 2(1.27,0)
  body extent -2.54,-1.27 2.54,1.27, height 8.54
